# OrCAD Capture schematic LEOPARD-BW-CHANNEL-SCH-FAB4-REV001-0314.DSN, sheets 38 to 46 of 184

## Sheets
38 141_PVCCIN_CPU0_MOSFET_1: size C; title: PVCCIN_CPU0_MOSFET_1
39 140_PVCCIN_CPU0_Controller: size A3; title: PVCCIN_CPU0_CONTROLLER
40 004_CLOCK BLOCK DIAGRAM: title: CLOCK BLOCK DIAGRAM
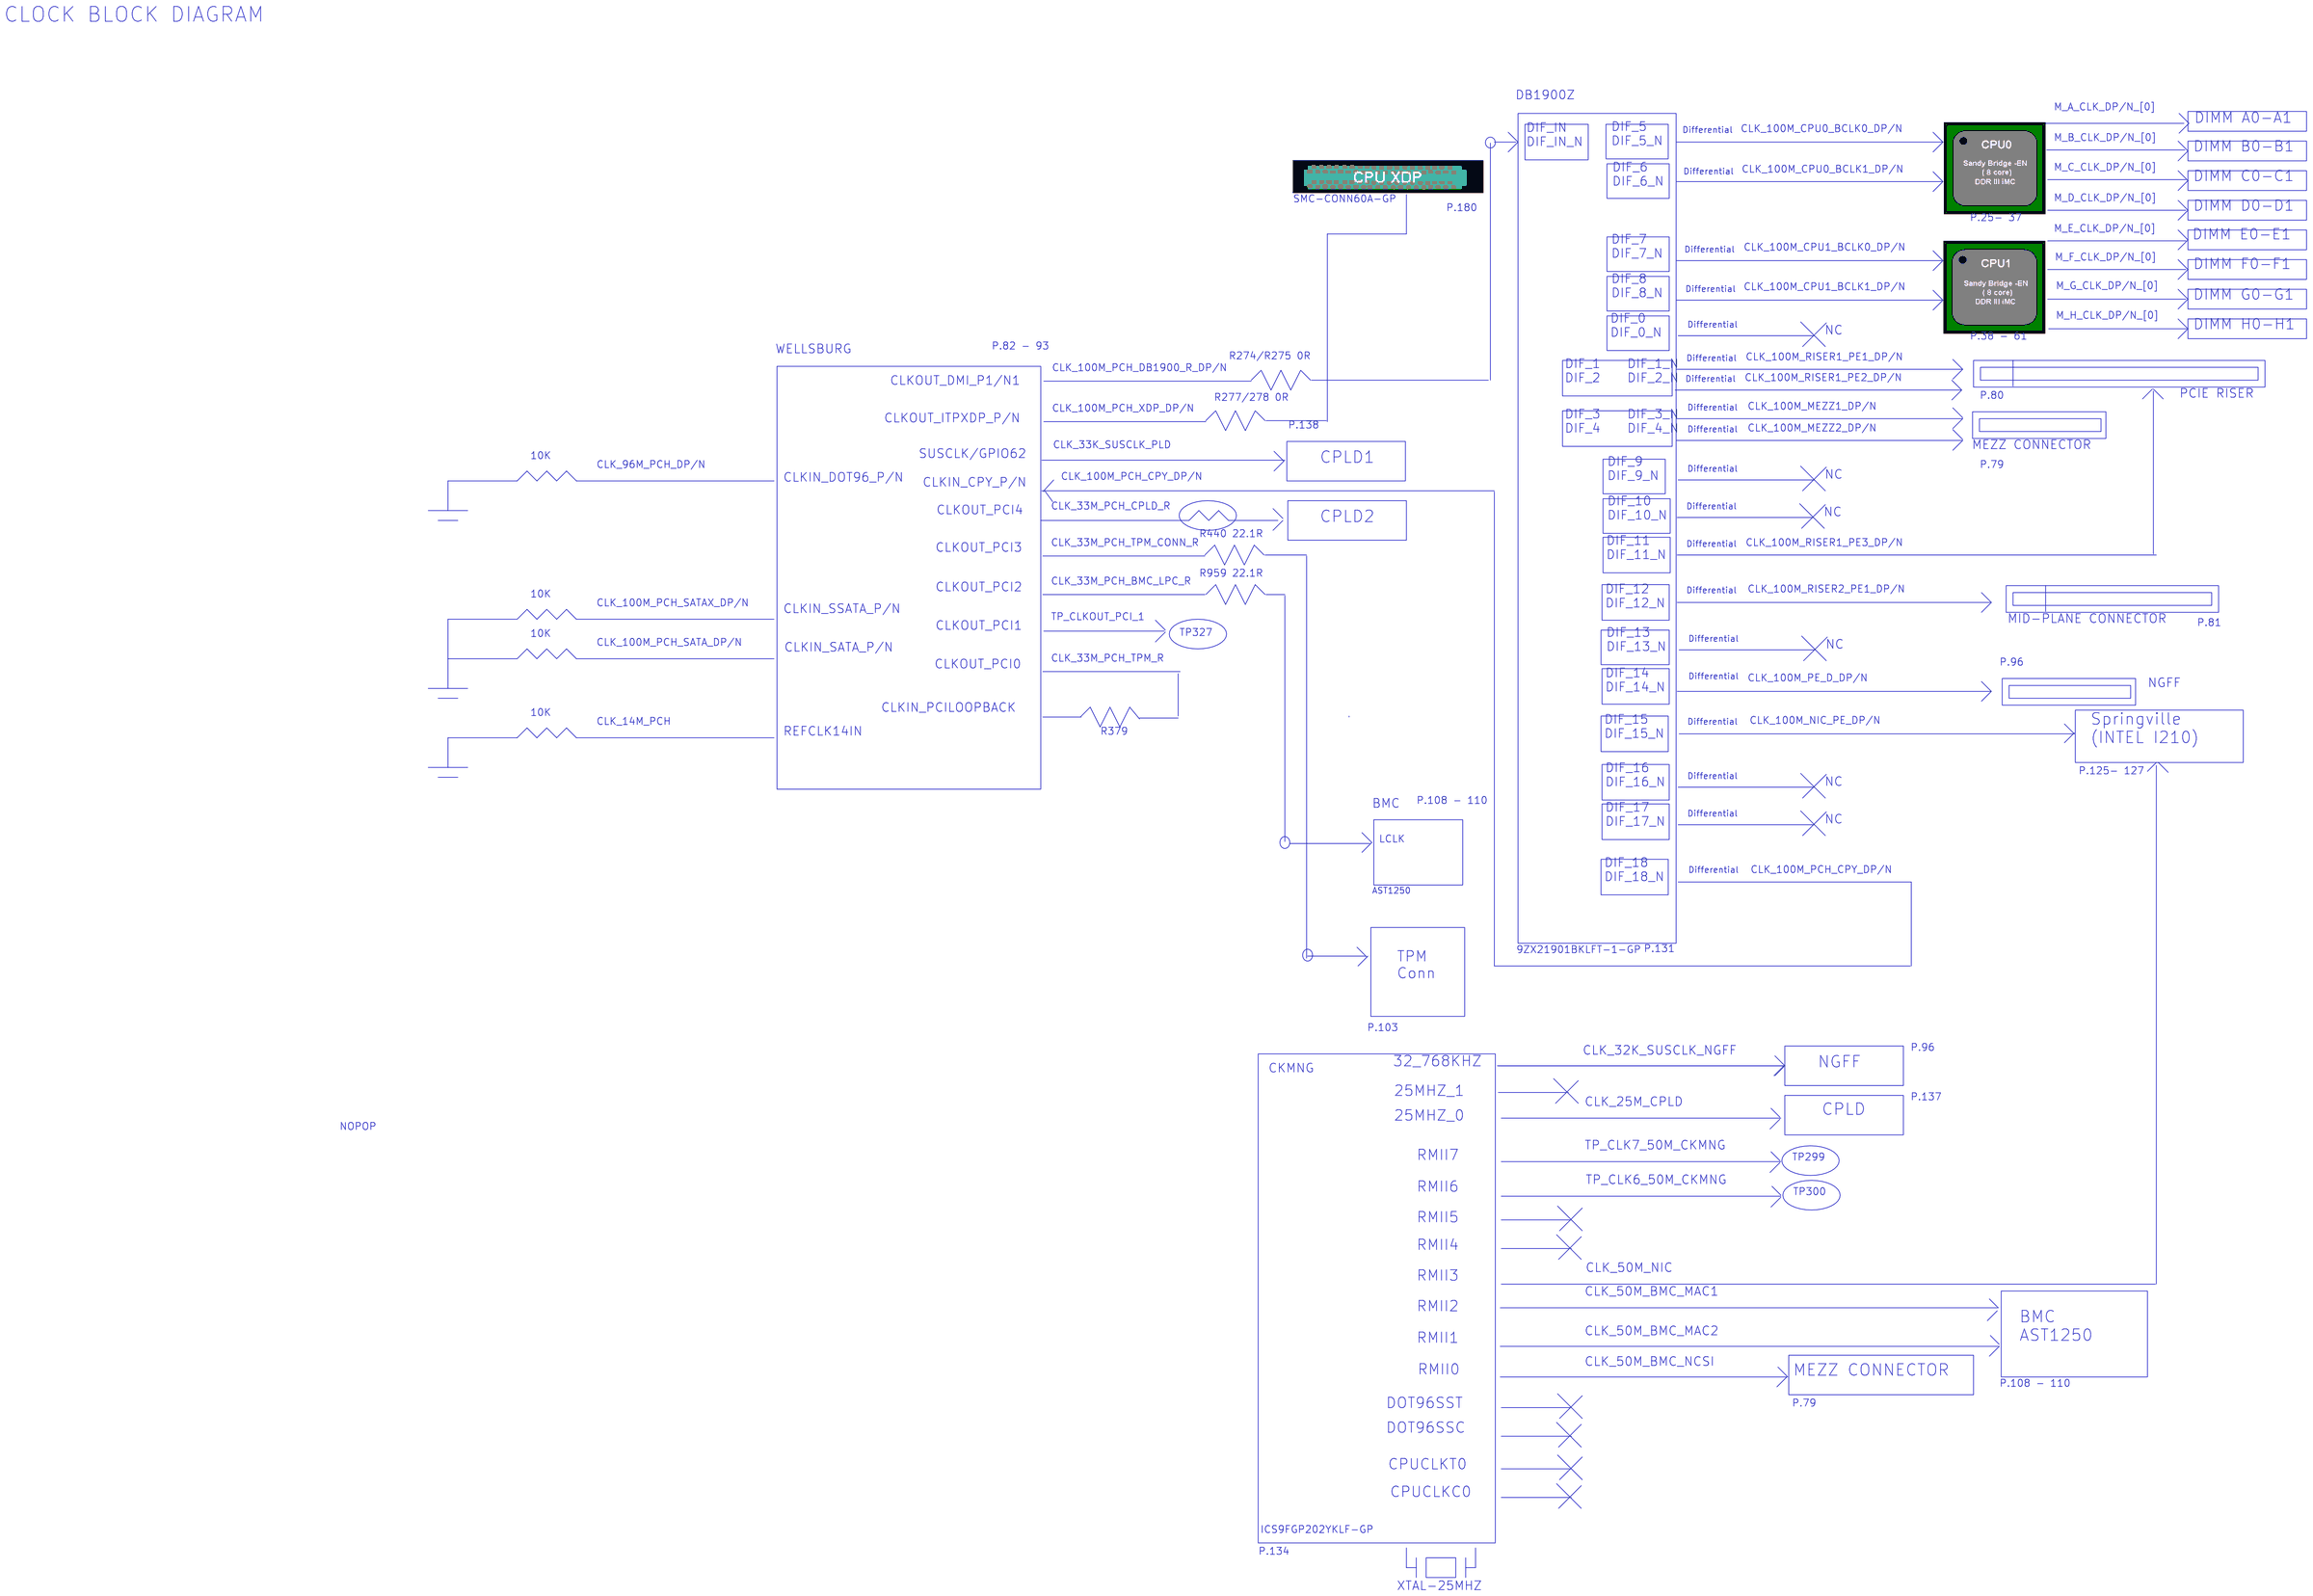
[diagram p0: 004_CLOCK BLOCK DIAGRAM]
41 007_SMBUS BLOCK DIAGRAM-CPU&PCH: title: SMBUS BLOCK DIAGRAM-CPU&PCH
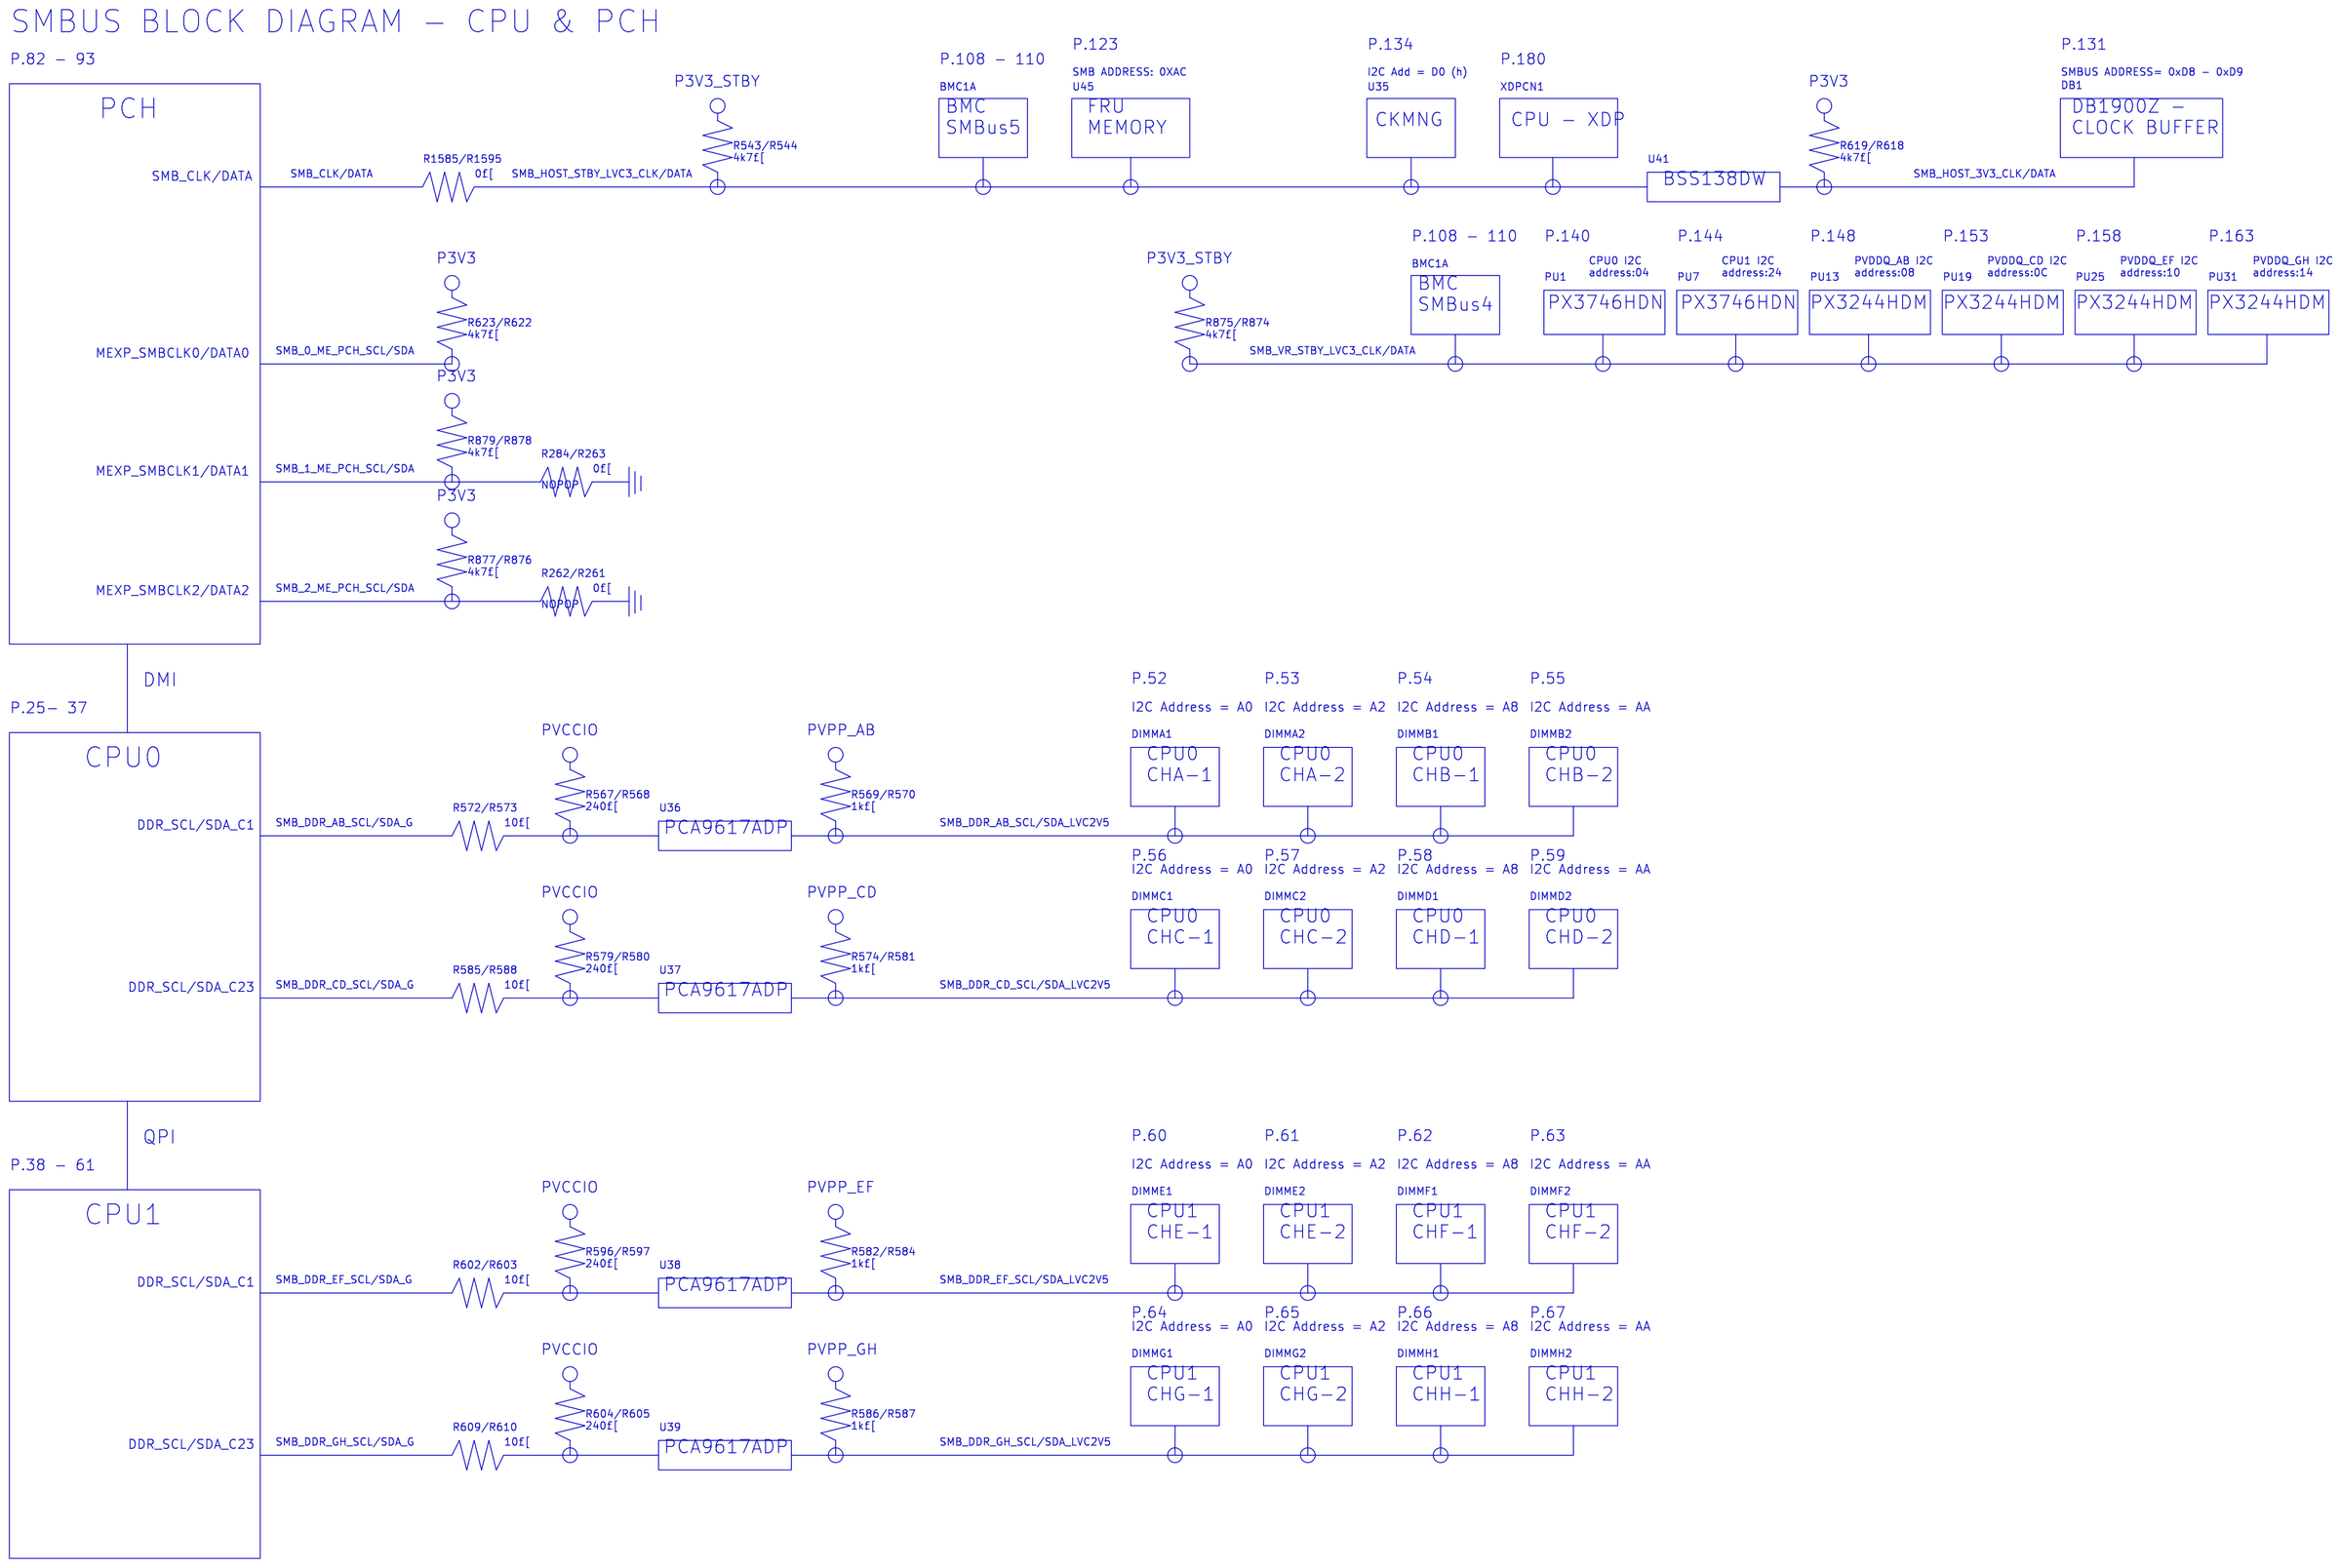
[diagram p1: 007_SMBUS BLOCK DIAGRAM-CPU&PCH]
42 006_SMBUS BLOCK DIAGRAM-BMC: title: SMBUS BLOCK DIAGRAM-BMC
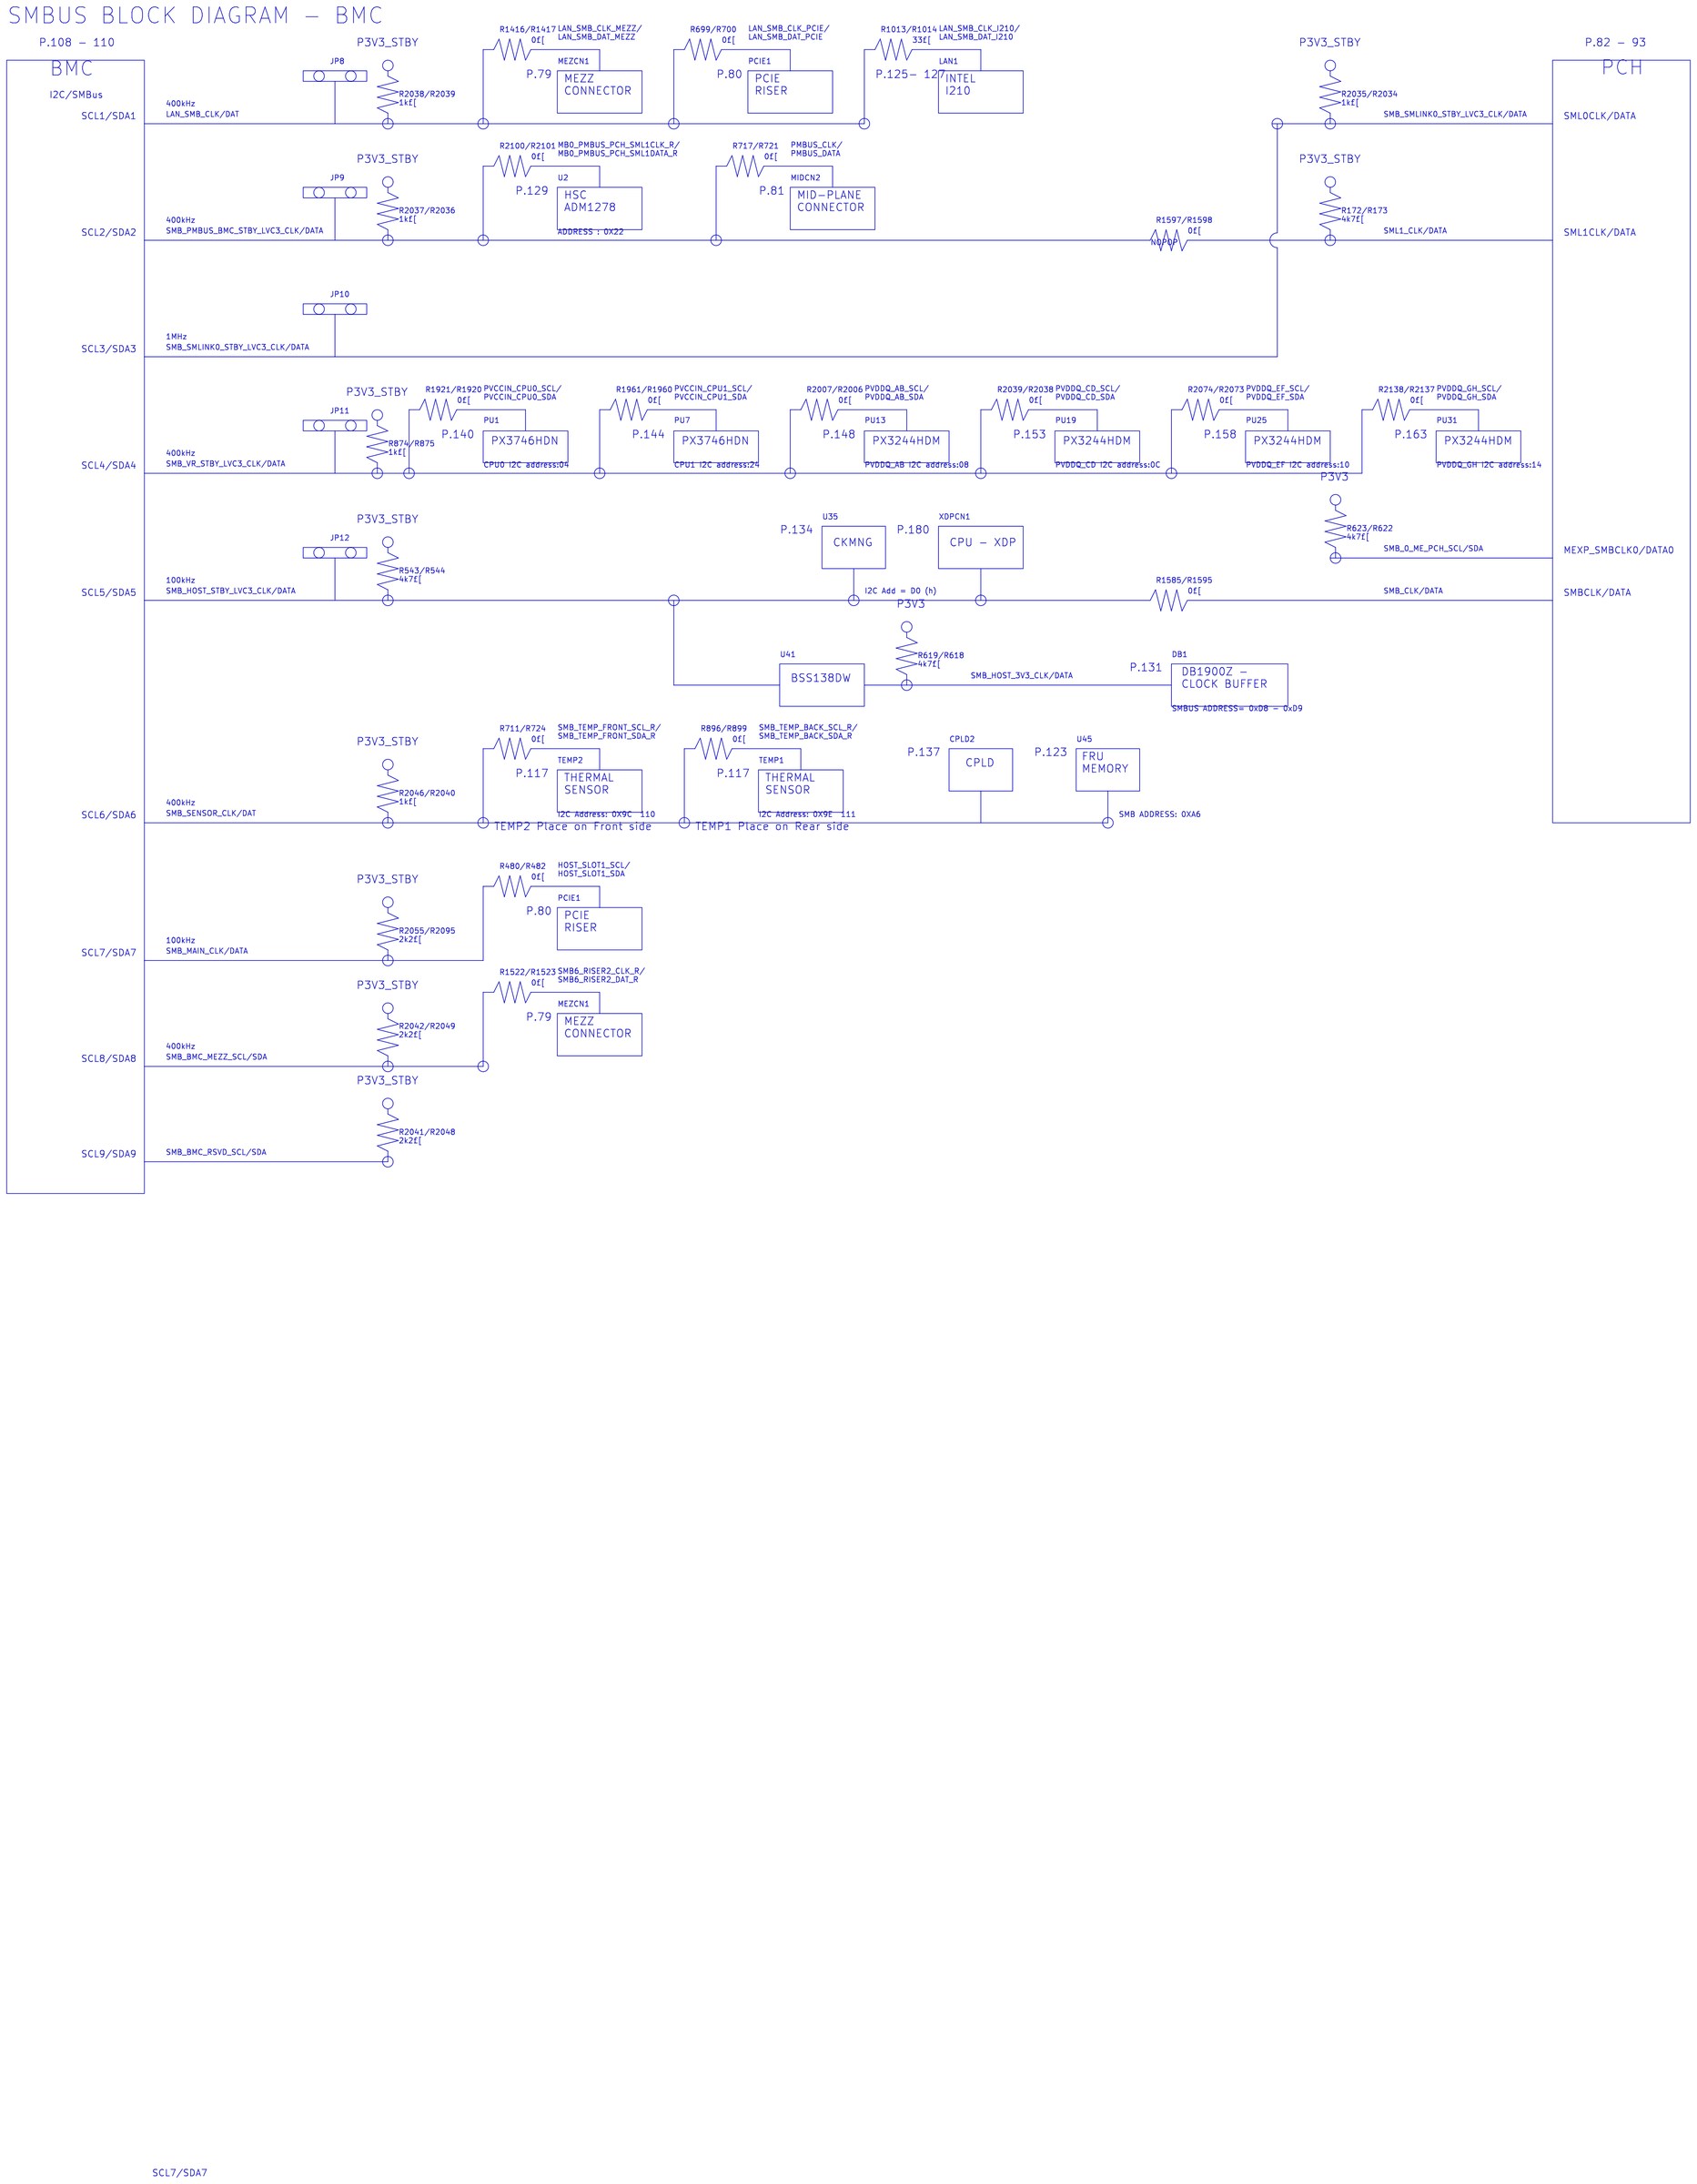
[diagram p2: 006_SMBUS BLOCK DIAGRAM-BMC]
43 184_CHANGE LIST: title: CHANGE LIST
44 183_SCREW HOLE: size A3; title: SCREW HOLE
45 182_POWER SEQUENCE CONTROL: size A3; title: POWER SEQUENCE CONTROL
46 181_CPU - JTAG: size A3; title: CPU - JTAG

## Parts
sheet 140_PVCCIN_CPU0_Controller
PC1087  SC1U10V2KX-4-GP  [C402H22]
PC1088  SCD1U16V2KX-3GP  [C402H22]
PC1089  SC1U10V2KX-4-GP  [C402H22]
PC1090  SCD1U16V2KX-3GP  [C402H22]
PC1094  SC1KP50V2KX-1GP  [C402H22]
PC1095  SC220P50V2KX-3GP  [C402H22]
PC1096  SC10U4V3MX-3-GP  [C603H40]
PC1097  SCD1U16V2KX-3GP  [C402H22]
PC1430  SC220P50V2JN-3GP  [C402H22]
PC1492  SC220P50V2JN-3GP  [C402H22]
PC7321  SCD47U6D3V2KX-1-GP  [C402H22]
PC7322  SCD47U6D3V2KX-1-GP  [C402H22]
PC7323  SCD47U6D3V2KX-1-GP  [C402H22]
PC7324  SCD47U6D3V2KX-1-GP  [C402H22]
PC7325  SCD47U6D3V2KX-1-GP  [C402H22]
PCN1  FCI-CON3-S1-GP  [68001-203HLF]
PQ5  NST3906F3T5G-GP-U  [SOT-1123CBE1006-1H16]
PR1911  0R2J-2-GP  [R402H16]
PR1914  1KR2F-3-GP  [R402H16]
PR1915  1KR2F-3-GP  [R402H16]
PR1916  0R2J-2-GP  [R402H16]
PR1917  0R2J-2-GP  [R402H16]
PR1918  0R2J-2-GP  [R402H16]
PR1922  16KR2F-GP  [R402H16]
PR1923  16KR2F-GP  [R402H16]
PR1924  16KR2F-GP  [R402H16]
PR1925  19K1R2F-GP  [R402H16]
PR1926  1KR2F-3-GP  [R402H16]
PR1927  10R3F-GP  [R603H22]
PR1928  0R2J-2-GP  [R402H16]
PR1929  0R0402-PAD-1-GP  [0R0402-PAD]
PR1931  49D9R2F-GP  [R402H16]
PR1932  100R2F-L1-GP-U  [R402H14]
PR1933  82R2J-1-GP  [R402H16]
PR1934  0R2J-2-GP  [R402H16]
PR1935  0R2J-2-GP  [R402H16]
PR1936  150R2F-1-GP  [R402H16]
PTP1  TPAD24  [TPAD24]
PU1  PX3746HDN-GP  [QFN48J6-G3437H36]
sheet 141_PVCCIN_CPU0_MOSFET_1
PC1221  SCD47U25V3KX-3-GP  [C603H36]
PC1222  SCD22U16V2KX-GP  [C402H22]
PC1227  SC1U10V2KX-4-GP  [C402H22]
PC1228  SC1U10V2KX-4-GP  [C402H22]
PC1229  SC10U16V5KX-1-GP  [C805H54]
PC1234  SCD47U25V3KX-3-GP  [C603H36]
PC1280  SC10U16V5KX-1-GP  [C805H54]
PC1281  SCD22U16V2KX-GP  [C402H22]
PC1282  SC1U10V2KX-4-GP  [C402H22]
PC1283  SC1U10V2KX-4-GP  [C402H22]
PC1284  SCD47U25V3KX-3-GP  [C603H36]
PC1362  SC10U16V5KX-1-GP  [C805H54]
PC1363  SC10U16V5KX-1-GP  [C805H54]
PC1364  SC10U16V5KX-1-GP  [C805H54]
PC1369  SC10U16V5KX-1-GP  [C805H54]
PC1370  SC10U16V5KX-1-GP  [C805H54]
PC1371  SC10U16V5KX-1-GP  [C805H54]
PC1372  SC10U16V5KX-1-GP  [C805H54]
PC1373  SCD22U16V2KX-GP  [C402H22]
PC1374  SC1U10V2KX-4-GP  [C402H22]
PC1375  SC1U10V2KX-4-GP  [C402H22]
PC1394  SCD1U16V2KX-3GP  [C402H22]
PC1395  SCD1U16V2KX-3GP  [C402H22]
PC1396  SC1U25V3KX-GP  [C603H36]
PC1403  SC1U25V3KX-GP  [C603H36]
PC1404  SC1U25V3KX-GP  [C603H36]
PC1405  SCD1U16V2KX-3GP  [C402H22]
PC1428  SCD1U16V2KX-3GP  [C402H22]
PC1429  SCD1U16V2KX-3GP  [C402H22]
PC1435  SCD1U16V2KX-3GP  [C402H22]
PG27  COPPER-CLOSE-GP-U  [CON2C-U]
PG28  COPPER-CLOSE-GP-U  [CON2C-U]
PG29  COPPER-CLOSE-GP-U  [CON2C-U]
PG30  COPPER-CLOSE-GP-U  [CON2C-U]
PG33  COPPER-CLOSE-GP-U  [CON2C-U]
PG34  COPPER-CLOSE-GP-U  [CON2C-U]
PL75  IND-150NH-15-GP  [L102078-254224H296]
PL76  IND-150NH-15-GP  [L102078-254224H296]
PL77  IND-150NH-15-GP  [L102078-254224H296]
PR24  0R2J-2-GP  [R402H16]
PR25  0R2J-2-GP  [R402H16]
PR26  0R2J-2-GP  [R402H16]
PR42  0R2J-2-GP  [R402H16]
PR43  0R2J-2-GP  [R402H16]
PR44  0R2J-2-GP  [R402H16]
PR2174  1R2F-GP  [R402H16]
PR2178  1R2F-GP  [R402H16]
PR2181  1R2F-GP  [R402H16]
PR2205  0R3J-6-GP  [R603H22]
PR2209  0R3J-6-GP  [R603H22]
PR2215  0R3J-6-GP  [R603H22]
PR2227  10KR2F-2-GP  [R402H16]
PR2228  10KR2F-2-GP  [R402H16]
PR2229  10KR2F-2-GP  [R402H16]
PR6626  562R2F-GP  [R402H16]
PR6627  562R2F-GP  [R402H16]
PR6629  562R2F-GP  [R402H16]
PR6630  562R2F-GP  [R402H16]
PR6631  562R2F-GP  [R402H16]
PR6632  562R2F-GP  [R402H16]
PTP7  TPAD24  [TPAD24]
PTP8  TPAD24  [TPAD24]
PTP9  TPAD24  [TPAD24]
PTP10  TPAD24  [TPAD24]
PTP11  TPAD24  [TPAD24]
PTP12  TPAD24  [TPAD24]
PU178  TDA21232-GP  [QFN31G5-G4P-7H38]
PU179  TDA21232-GP  [QFN31G5-G4P-7H38]
PU180  TDA21232-GP  [QFN31G5-G4P-7H38]
sheet 181_CPU - JTAG
C714  SC1U25V3KX-GP  [C603H36]
C715  SCD01U25V2KX-3GP  [C402H22]
C716  SC1U25V3KX-GP  [C603H36]
C717  SCD01U25V2KX-3GP  [C402H22]
C722  SC1U25V3KX-GP  [C603H36]
C727  SC1U25V3KX-GP  [C603H36]
C909  SC1U25V3KX-GP  [C603H36]
R300  0R2J-2-GP  [R402H16]
R303  0R2J-2-GP  [R402H16]
R328  0R2J-2-GP  [R402H16]
R329  0R2J-2-GP  [R402H16]
R426  0R2J-2-GP  [R402H16]
R431  0R2J-2-GP  [R402H16]
R470  2KR2F-3-GP  [R402H16]
R612  51R2F-2-GP  [R402H16]
R615  51R2F-2-GP  [R402H16]
R626  51R2F-2-GP  [R402H16]
R702  100R2F-L1-GP-U  [R402H14]
R1000  75R2F-2-GP  [R402H16]
R1001  75R2F-2-GP  [R402H16]
R1003  75R2F-2-GP  [R402H16]
R1006  1KR2F-3-GP  [R402H16]
R1007  1KR2F-3-GP  [R402H16]
R1213  1KR2F-3-GP  [R402H16]
R1214  1KR2F-3-GP  [R402H16]
R1237  100R2F-L1-GP-U  [R402H14]
R1245  100R2F-L1-GP-U  [R402H14]
R1246  100R2F-L1-GP-U  [R402H14]
R1247  1KR2F-3-GP  [R402H16]
TP313  TPAD24  [TPAD24]
TP314  TPAD24  [TPAD24]
U69  NC7SB3157P6X-2GP  [UMT6H44]
U70  NC7SB3157P6X-2GP  [UMT6H44]
U71  74LVC1G02GW-1-GP  [SC70-5H44]
U72  NC7SZ66P5X-1GP  [SC70-5H44]
U146  GTL2034PW-GP  [TSOIC14H44]
sheet 182_POWER SEQUENCE CONTROL
D15  BAT54-7-F-GP  [SOT-23-6H44]
D16  BAT54-7-F-GP  [SOT-23-6H44]
D17  BAT54-7-F-GP  [SOT-23-6H44]
D18  BAT54-7-F-GP  [SOT-23-6H44]
D19  BAT54-7-F-GP  [SOT-23-6H44]
D33  BAT54-7-F-GP  [SOT-23-6H44]
D34  BAT54-7-F-GP  [SOT-23-6H44]
D35  BAT54-7-F-GP  [SOT-23-6H44]
sheet 183_SCREW HOLE
CLIP1  AMP-CON2-13-GP  [G800U305032D1EU]
CLIP2  AMP-CON2-13-GP  [G800U305032D1EU]
H1  GEN276X162R197X296-6-F-A-GP  [GEN276X162R197X296-6-F-A]
H2  GEN276X162R197X296-6-F-A-GP  [GEN276X162R197X296-6-F-A]
H3  GEN276X162R197X296-6-F-A-GP  [GEN276X162R197X296-6-F-A]
H4  GEN276X162R197X296-6-F-A-GP  [GEN276X162R197X296-6-F-A]
H5  GEN276X162R197X296-6-F-A-GP  [GEN276X162R197X296-6-F-A]
H6  GEN276X162R197X296-6-F-A-GP  [GEN276X162R197X296-6-F-A]
H7  GEN276X162R197X296-6-F-A-GP  [GEN276X162R197X296-6-F-A]
H8  STFT363B238R224H453-GP  [STFT363B238R224H453]
H10  HOLE  [HOLE256R126]

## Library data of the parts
PC1087 PC1089 PC1227 PC1228 PC1282 PC1283 PC1374 PC1375 = SC1U10V2KX-4-GP: CHIP CAP C 1U 10V K 0402 X6S; GREENDFACTOR: R2_SA;HF_SA;; Package Type: SMD-BCG6; Part Number: 78.10523.8FL; SPEC: http://wpqssvr.wistron.com.tw:7001/wpqs/servlet/COM.qpart.Attachment?PartNumber=78.10523.8FL
PC1088 PC1090 = SCD1U16V2KX-3GP: CHIP CAP C 0.1U 16V K0402 X7R; GREENDFACTOR: R2_SA;HF_SA;G_SA;; MAIN_SOURCE: M; Package Type: SMD-BCG; Part Number: 78.10421.2FL; SPEC: http://wpqssvr.wistron.com.tw:7001/wpqs/servlet/COM.qpart.Attachment?PartNumber=78.10421.2FL
PC1094 = SC1KP50V2KX-1GP: CHIP CAP 1000P50V K0402 X7R(RO; GREENDFACTOR: R2_SA;HF_SA;G_SA;; MAIN_SOURCE: M; Package Type: SMD-BCG; Part Number: 78.10224.2FL; SPEC: http://wpqssvr.wistron.com.tw:7001/wpqs/servlet/COM.qpart.Attachment?PartNumber=78.10224.2FL
PC1095 = SC220P50V2KX-3GP: CHIP CAP 220P50V K0402 X7R(ROH; GREENDFACTOR: R2_SA;HF_SA;G_SA;; MAIN_SOURCE: M; Package Type: SMD-BCG; Part Number: 78.22124.2FL; SPEC: http://wpqssvr.wistron.com.tw:7001/wpqs/servlet/COM.qpart.Attachment?PartNumber=78.22124.2FL
PC1096 = SC10U4V3MX-3-GP: CHIP CAP C 10U 4V M0603 X6S; GREENDFACTOR: R2_C;; POP?: 078.1061T.08B1; Package Type: SMD-BCG6; Part Number: 78.1061T.8BL; SPEC: http://wpqssvr.wistron.com.tw:7001/wpqs/servlet/COM.qpart.Attachment?PartNumber=78.1061T.8BL
PC1097 = SCD1U16V2KX-3GP: CHIP CAP C 0.1U 16V K0402 X7R; CATEGORIES: CAP_1.xV; GREENDFACTOR: R2_SA;HF_SA;G_SA;; MAIN_SOURCE: M; Part Number: 78.10421.2FL; Part Type: SMD-BCG; SPEC: http://wpqssvr.wistron.com.tw:7001/wpqs/servlet/COM.qpart.Attachment?PartNumber=78.10421.2FL
PC1430 PC1492 = SC220P50V2JN-3GP: CHIP CAP C 220P 50V J0402 NPO; GREENDFACTOR: R2_SA;HF_SA;G_SA;; Package Type: SMD-BCG; Part Number: 78.22134.1FL; SPEC: http://wpqssvr.wistron.com.tw:7001/wpqs/servlet/COM.qpart.Attachment?PartNumber=78.22134.1FL
PC7321-PC7325 = SCD47U6D3V2KX-1-GP: CHIP CAP C 0.47U 6.3V K 0402 X6S; GREENDFACTOR: R2_SA;HF_SA;; Package Type: SMD-BCG3; Part Number: 78.47420.8FL; SPEC: http://wpqssvr.wistron.com.tw:7001/wpqs/servlet/COM.qpart.Attachment?PartNumber=78.47420.8FL
PCN1 = FCI-CON3-S1-GP: HEAD ML 1R3P ST 68001-203HLF; GREENDFACTOR: R2_SA;; Part Number: 21.61084.103; Part Type: CONN-G4; SPEC: http://wpqssvr.wistron.com.tw:7001/wpqs/servlet/COM.qpart.Attachment?PartNumber=21.61084.103
PQ5 = NST3906F3T5G-GP-U: XTOR NST3906F3T5G PNP SOT-1123; GREENDFACTOR: R2_SA;HF_SA;; Package Type: DISCRET-G5; Part Number: 84.03906.01K; SPEC: http://wpqssvr.wistron.com.tw:7001/wpqs/servlet/COM.qpart.Attachment?PartNumber=84.03906.01K
PR42-PR44 PR1911 PR1916-PR1918 PR1934 PR1935 = 0R2J-2-GP: CHIP RES 0 J 1/16W 0402; GREENDFACTOR: R2_SA;HF_SA;G_SA;; Package Type: SMD-RG; Part Number: 63.R0034.1DL; SPEC: http://wpqssvr.wistron.com.tw:7001/wpqs/servlet/COM.qpart.Attachment?PartNumber=63.R0034.1DL
PR1914 PR1915 PR1926 = 1KR2F-3-GP: CHIP RES 1K F 1/16W 0402; GREENDFACTOR: R2_SA;HF_SA;G_SA;; Package Type: SMD-RG; Part Number: 64.10015.6DL; SPEC: http://wpqssvr.wistron.com.tw:7001/wpqs/servlet/COM.qpart.Attachment?PartNumber=64.10015.6DL
PR1922 PR1923 = 16KR2F-GP: CHIP RES 16K F 1/16W 0402; GREENDFACTOR: R2_SA;HF_SA;G_SA;; Module: VR_PVCORE_CPU; POP?: NOPOP; Package Type: SMD-RG; Part Number: 64.16025.6DL; Quotation: 8_1; SPEC: http://wpqssvr.wistron.com.tw:7001/wpqs/servlet/COM.qpart.Attachment?PartNumber=64.16025.6DL
PR1924 = 16KR2F-GP: CHIP RES 16K F 1/16W 0402; GREENDFACTOR: R2_SA;HF_SA;G_SA;; Module: VR_PVCORE_CPU; Package Type: SMD-RG; Part Number: 64.16025.6DL; Quotation: 8_1; SPEC: http://wpqssvr.wistron.com.tw:7001/wpqs/servlet/COM.qpart.Attachment?PartNumber=64.16025.6DL
PR1925 = 19K1R2F-GP: CHIP RES 19.1K F 1/16W 0402; GREENDFACTOR: R2_SA;HF_SA;G_SA;; Part Number: 64.19125.6DL; Part Type: RCL_GP; SPEC: http://wpqssvr.wistron.com.tw:7001/wpqs/servlet/COM.qpart.Attachment?PartNumber=64.19125.6DL
PR1927 = 10R3F-GP: CHIP RES 10 F 1/10W 0603; GREENDFACTOR: R2_SA;HF_SA;G_SA;; Level: SMD; Package Type: RCL_GP; Part Number: 64.10R05.55L; Part Type: RCL_GP; SPEC: http://wpqssvr.wistron.com.tw:7001/wpqs/servlet/COM.qpart.Attachment?PartNumber=64.10R05.55L; Status: POP
PR1928 = 0R2J-2-GP: CHIP RES 0 J 1/16W 0402; GREENDFACTOR: R2_SA;HF_SA;G_SA;; Part Number: 63.R0034.1DL; Part Type: SMD-RG; SPEC: http://wpqssvr.wistron.com.tw:7001/wpqs/servlet/COM.qpart.Attachment?PartNumber=63.R0034.1DL
PR1929 = 0R0402-PAD-1-GP: DUMMY PAD WITH WIRE RES 0 0402; GREENDFACTOR: R_C;; Module: VR_CPU_PVCC; Package Type: SMD-RG2; Part Number: ZZ.R0402.001; Part Type: SMD-RG2; Quotation: 8_1; SPEC: http://wpqssvr.wistron.com.tw:7001/wpqs/servlet/COM.qpart.Attachment?PartNumber=ZZ.R0402.001
PR1931 = 49D9R2F-GP: CHIP RES 49.9 F 1/16W 0402; GREENDFACTOR: R2_SA;HF_SA;G_SA;; Package Type: RCL_GP; Part Number: 64.49R95.6DL; SPEC: http://wpqssvr.wistron.com.tw:7001/wpqs/servlet/COM.qpart.Attachment?PartNumber=64.49R95.6DL
PR1932 = 100R2F-L1-GP-U: CHIP RES 100 F 1/16W 0402; GREENDFACTOR: R2_SA;HF_SA;G_SA;; Package Type: SMD-RG; Part Number: 64.10005.6DL; SPEC: http://wpqssvr.wistron.com.tw:7001/wpqs/servlet/COM.qpart.Attachment?PartNumber=64.10005.6DL
PR1933 = 82R2J-1-GP: CHIP RES 82 J 1/16W 0402; GREENDFACTOR: R2_SA;HF_SA;G_SA;; POP?: NOPOP; Package Type: RCL_GP; Part Number: 63.82034.1DL; SPEC: http://wpqssvr.wistron.com.tw:7001/wpqs/servlet/COM.qpart.Attachment?PartNumber=63.82034.1DL
PR1936 = 150R2F-1-GP: CHIP RES 150 F 1/16W 0402; GREENDFACTOR: R2_SA;HF_SA;G_SA;; Package Type: SMD-RG; Part Number: 64.15005.6DL; SPEC: http://wpqssvr.wistron.com.tw:7001/wpqs/servlet/COM.qpart.Attachment?PartNumber=64.15005.6DL
PTP1 PTP7-PTP12 = TPAD24: 24 MILS TEST PAD; GREENDFACTOR: Regular;; Package Type: DISCRET2; Part Number: ZZ.PAD24.001; SPEC: http://wpqssvr.wistron.com.tw:7001/wpqs/servlet/COM.qpart.Attachment?PartNumber=ZZ.PAD24.001
PU1 = PX3746HDN-GP: IC PWM CTRL PX3746HDN QFN 48P; GREENDFACTOR: R2_SA;; Package Type: ASIC-G5; Part Number: 074.03746.0073; SPEC: http://wpqssvr.wistron.com.tw:7001/wpqs/servlet/COM.qpart.Attachment?PartNumber=074.03746.0073
PC1221 PC1234 PC1284 = SCD47U25V3KX-3-GP: CHIP CAP C 0.47U 25V K0603 X7R; GREENDFACTOR: R2_SA;HF_SA;G_SA;; Part Number: 78.47422.2BL; Part Type: SMD-BCG5; SPEC: http://wpqssvr.wistron.com.tw:7001/wpqs/servlet/COM.qpart.Attachment?PartNumber=78.47422.2BL
PC1222 PC1281 PC1373 = SCD22U16V2KX-GP: CHIP CAP C 0.22U 16V K0402 X7R; GREENDFACTOR: R2_SA;HF_SA;G_SA;; Package Type: SMD-BCG4; Part Number: 78.22421.2FL; SPEC: http://wpqssvr.wistron.com.tw:7001/wpqs/servlet/COM.qpart.Attachment?PartNumber=78.22421.2FL; Size: 0402; Type: X7R
PC1229 PC1280 PC1362-PC1364 PC1369-PC1372 = SC10U16V5KX-1-GP: CHIP CAP C 10U 16V K0805 X6S; GREENDFACTOR: R2_SA;; Package Type: SMD-BCG5; Part Number: 78.10621.81L; SPEC: http://wpqssvr.wistron.com.tw:7001/wpqs/servlet/COM.qpart.Attachment?PartNumber=78.10621.81L
PC1394 PC1395 PC1405 PC1428 PC1429 PC1435 = SCD1U16V2KX-3GP: CHIP CAP C 0.1U 16V K0402 X7R; GREENDFACTOR: R2_SA;HF_SA;G_SA;; MAIN_SOURCE: M; Package Type: SMD-BCG; Part Number: 78.10421.2FL; SPEC: http://wpqssvr.wistron.com.tw:7001/wpqs/servlet/COM.qpart.Attachment?PartNumber=78.10421.2FL; Size: 0402; Type: X7R
PC1396 PC1403 PC1404 = SC1U25V3KX-GP: CHIP CAP C 1U 25V K0603 X7R; GREENDFACTOR: R2_SA;HF_SA;G_SA;; Package Type: SMD-BCG; Part Number: 78.10522.2BL; SPEC: http://wpqssvr.wistron.com.tw:7001/wpqs/servlet/COM.qpart.Attachment?PartNumber=78.10522.2BL
PG27-PG30 PG33 PG34 = COPPER-CLOSE-GP-U: COPPER CLOSE; GREENDFACTOR: Regular;; Package Type: DISCRET-G9; Part Number: ZZ.CON2C.XXX; SPEC: http://wpqssvr.wistron.com.tw:7001/wpqs/servlet/COM.qpart.Attachment?PartNumber=ZZ.CON2C.XXX
PL75-PL77 = IND-150NH-15-GP: CHIP IND 150NH K FP1007R3-R15-R; GREENDFACTOR: R2_SA;; Part Number: 68.1512N.10E; Part Type: DISCRET-G9; SPEC: http://wpqssvr.wistron.com.tw:7001/wpqs/servlet/COM.qpart.Attachment?PartNumber=68.1512N.10E
PR24-PR26 = 0R2J-2-GP: CHIP RES 0 J 1/16W 0402; GREENDFACTOR: R2_SA;HF_SA;G_SA;; POP?: NOPOP; Package Type: SMD-RG; Part Number: 63.R0034.1DL; SPEC: http://wpqssvr.wistron.com.tw:7001/wpqs/servlet/COM.qpart.Attachment?PartNumber=63.R0034.1DL
PR2174 PR2178 PR2181 = 1R2F-GP: CHIP RES 1 F 1/16W 0402; GREENDFACTOR: R2_SA;HF_SA;G_SA;; Package Type: SMD-RG; Part Number: 64.1R005.6DL; SPEC: http://wpqssvr.wistron.com.tw:7001/wpqs/servlet/COM.qpart.Attachment?PartNumber=64.1R005.6DL
PR2205 PR2209 PR2215 = 0R3J-6-GP: CHIP RES 0 J 1/10W 0603; GREENDFACTOR: R2_SA;HF_SA;G_SA;; Part Number: 63.R0033.15L; Part Type: SMD-RG1; SPEC: http://wpqssvr.wistron.com.tw:7001/wpqs/servlet/COM.qpart.Attachment?PartNumber=63.R0033.15L
PR2227-PR2229 = 10KR2F-2-GP: CHIP RES 10K F 1/16W 0402; GREENDFACTOR: R2_SA;HF_SA;G_SA;; POP?: NOPOP; Package Type: SMD-RG; Part Number: 64.10025.6DL; SPEC: http://wpqssvr.wistron.com.tw:7001/wpqs/servlet/COM.qpart.Attachment?PartNumber=64.10025.6DL
PR6626 PR6627 PR6629-PR6632 = 562R2F-GP: CHIP RES 562 F 1/16W 0402; GREENDFACTOR: R2_SA;HF_SA;G_SA;; Package Type: SMD-RG; Part Number: 64.56205.6DL; SPEC: http://wpqssvr.wistron.com.tw:7001/wpqs/servlet/COM.qpart.Attachment?PartNumber=64.56205.6DL
PU178-PU180 = TDA21232-GP: IC PWM TDA21232 IQFN 32P; GREENDFACTOR: R2_C;; Part Number: 074.21232.0073; Part Type: DISCRET-GB1; SPEC: http://wpqssvr.wistron.com.tw:7001/wpqs/servlet/COM.qpart.Attachment?PartNumber=074.21232.0073
C714 C716 C722 C727 C909 = SC1U25V3KX-GP: CHIP CAP C 1U 25V K0603 X7R; GREENDFACTOR: R2_SA;HF_SA;G_SA;; Part Number: 78.10522.2BL; Part Type: SMD-BCG; SPEC: http://wpqssvr.wistron.com.tw:7001/wpqs/servlet/COM.qpart.Attachment?PartNumber=78.10522.2BL
C715 C717 = SCD01U25V2KX-3GP: CHIP 0.01U 25V K0402 X7R(ROHS); Category: XDP; DESCRIPTIO: CHIP 0.01U 25V K0402 X7R(ROHS); GREENDFACTOR: R2_SA;HF_SA;G_SA;; Package Type: SMD-BCG; Part Number: 78.10322.2FL; Part Type: SMD-BCG; SPEC: http://wpqssvr.wistron.com.tw:7001/wpqs/servlet/COM.qpart.Attachment?PartNumber=78.10322.2FL; VENDORPARTNUMBER: 04023C103KAT2A/C1005X7R103KFT/GRM155R71E103KA01D/223891715636/CL05B103KA5NNNC/TMK105BJ103KV-F/C1005X7R1E103KT000F
R300 R328 = 0R2J-2-GP: CHIP RES 0 J 1/16W 0402; Category: PCH; DESCRIPTIO: CHIP RES 0 J 1/16W 0402; GREENDFACTOR: R2_SA;HF_SA;G_SA;; Package Type: SMD-RG; Part Number: 63.R0034.1DL; Part Type: SMD-RG; SPEC: http://wpqssvr.wistron.com.tw:7001/wpqs/servlet/COM.qpart.Attachment?PartNumber=63.R0034.1DL; VENDORPARTNUMBER: RM04JTN0/RTT02000JTH/RR0510X-000-XN/RC0402JR-070RL/WR04X000 PTL
R303 R329 = 0R2J-2-GP: CHIP RES 0 J 1/16W 0402; Category: PCH; DESCRIPTIO: CHIP RES 0 J 1/16W 0402; GREENDFACTOR: R2_SA;HF_SA;G_SA;; POP?: NOPOP; Package Type: SMD-RG; Part Number: 63.R0034.1DL; Part Type: SMD-RG; SPEC: http://wpqssvr.wistron.com.tw:7001/wpqs/servlet/COM.qpart.Attachment?PartNumber=63.R0034.1DL; VENDORPARTNUMBER: RM04JTN0/RTT02000JTH/RR0510X-000-XN/RC0402JR-070RL/WR04X000 PTL
R426 R431 = 0R2J-2-GP: CHIP RES 0 J 1/16W 0402; Category: LOM - i350; DESCRIPTIO: CHIP RES 0 J 1/16W 0402; GREENDFACTOR: R2_SA;HF_SA;G_SA;; POP?: NOPOP; Package Type: SMD-RG; Part Number: 63.R0034.1DL; Part Type: SMD-RG; SPEC: http://wpqssvr.wistron.com.tw:7001/wpqs/servlet/COM.qpart.Attachment?PartNumber=63.R0034.1DL; VENDORPARTNUMBER: RM04JTN0/RTT02000JTH/RR0510X-000-XN/RC0402JR-070RL/WR04X000 PTL
R470 = 2KR2F-3-GP: CHIP RES 2K F 1/16W 0402; Category: internal conn; DESCRIPTIO: CHIP RES 2K F 1/16W 0402; GREENDFACTOR: R2_SA;HF_SA;G_SA;; Package Type: SMD-RG; Part Number: 64.20015.6DL; Part Type: SMD-RG; SPEC: http://wpqssvr.wistron.com.tw:7001/wpqs/servlet/COM.qpart.Attachment?PartNumber=64.20015.6DL; VENDORPARTNUMBER: RM04FTN2001 / RTT022001FTH / RR0510S-202-FN / RC0402FR-072KL/WR04X2001FTL
R612 R615 R626 = 51D1R2F-GP: CHIP RES 51 F 1/16W 0402; Category: XDP; DESCRIPTIO: CHIP RES 51.1 F 1/16W 0402; GREENDFACTOR: R2_SA;HF_SA;G_SA;; Package Type: SMD-RG; Part Number: 64.51R05.6DL; Part Type: SMD-RG; SPEC: http://wpqssvr.wistron.com.tw:7001/wpqs/servlet/COM.qpart.Attachment?PartNumber=64.51R05.6DL; VENDORPARTNUMBER: RM04FTN51R0/RTT0251R0FTH/RR0510S-510-FN/RC0402FR-0751RL/WR04X51R0FTL
R702 R1237 R1245 R1246 = 100R2F-L1-GP-U: CHIP RES 100 F 1/16W 0402; Category: BMC; DESCRIPTIO: CHIP RES 100 F 1/16W 0402; GREENDFACTOR: R2_SA;HF_SA;G_SA;; Package Type: SMD-RG; Part Number: 64.10005.6DL; Part Type: SMD-RG; SPEC: http://wpqssvr.wistron.com.tw:7001/wpqs/servlet/COM.qpart.Attachment?PartNumber=64.10005.6DL; VENDORPARTNUMBER: RM04FTN1000 / RTT021000FTH / RR0510S-1000-FN / RC0402FR-07100RL/WR04X1000FTL
R1000 R1001 R1003 = 75R2F-2-GP: CHIP RES 75 F 1/16W 0402; Category: XDP; DESCRIPTIO: CHIP RES 75 F 1/16W 0402; GREENDFACTOR: R2_SA;HF_SA;G_SA;; Package Type: SMD-RG; Part Number: 64.75R05.6DL; Part Type: SMD-RG; SPEC: http://wpqssvr.wistron.com.tw:7001/wpqs/servlet/COM.qpart.Attachment?PartNumber=64.75R05.6DL; VENDORPARTNUMBER: RM04FTN75R0 / RTT0275R0FTH / RR0510S-750-FN / RC0402FR-0775RL/WR04X75R0FTL
R1006 R1007 R1213 R1214 R1247 = 1KR2F-3-GP: CHIP RES 1K F 1/16W 0402; Category: internal conn; GREENDFACTOR: R2_SA;HF_SA;G_SA;; Package Type: SMD-RG; Part Number: 64.10015.6DL; Part Type: SMD-RG; SPEC: http://wpqssvr.wistron.com.tw:7001/wpqs/servlet/COM.qpart.Attachment?PartNumber=64.10015.6DL; VENDORPARTNUMBER: RM04FTN1001 / RTT021001FTH / RR0510S-1001-FN / RC0402FR-071KL/WR04X1001FTL
TP313 TP314 = TPAD24: 24 MILS TEST PAD; Part Number: ZZ.PAD24.001; Part Type: DISCRET2
U69 U70 = NC7SB3157P6X-2GP: IC SW NC7SB3157P6X SC70(L/F); Alternate: 73.03157.B0H; Category: XDP; Change to: 73.03157.A0J; DESCRIPTIO: IC SW NC7SB3157P6X SC70(L/F); GREENDFACTOR: R2_SA;; Note: The same as CRB; Package Type: DISCRET-G; Part Number: 73.03157.D0H; Part Type: DISCRET-G; SPEC: http://wpqssvr.wistron.com.tw:7001/wpqs/servlet/COM.qpart.Attachment?PartNumber=73.03157.D0H; VENDORPARTNUMBER: NC7SB3157P6X
U71 = 74LVC1G02GW-1-GP: IC CMOS 74LVC1G02GW SOT353-1; Alternate: 73.01G02.DHH,73.7SZ02.BAH; Category: CPU; DESCRIPTIO: IC CMOS 74LVC1G02GW SOT353-1; GREENDFACTOR: R2_SA;; Note: The same as CRB; Package Type: DISCRET-G2; Part Number: 73.01G02.AHG; Part Type: DISCRET-G2; SPEC: http://wpqssvr.wistron.com.tw:7001/wpqs/servlet/COM.qpart.Attachment?PartNumber=73.01G02.AHG; VENDORPARTNUMBER: 74LVC1G02GW
U72 = NC7SZ66P5X-1GP: IC CMOS NC7SZ66P5X_NL SC70(L/F; Category: XDP; Change to: 73.01G66.DHH; DESCRIPTIO: IC CMOS NC7SZ66P5X_NL SC70(L/F; GREENDFACTOR: R2_SA;; Note: (1) The same as L82TT1 (2) Alternate also the same as L82TT1.; Package Type: DISCRET-G; Part Number: 73.7SZ66.AAH; Part Type: DISCRET-G; SPEC: http://wpqssvr.wistron.com.tw:7001/wpqs/servlet/COM.qpart.Attachment?PartNumber=73.7SZ66.AAH; VENDORPARTNUMBER: NC7SZ66P5X_NL
U146 = GTL2034PW-GP: IC XLATOR GTL2034PW TSSOP 14P; GREENDFACTOR: R_C;; Package Type: TTL-G3; Part Number: 71.02034.00W; SPEC: http://wpqssvr.wistron.com.tw:7001/wpqs/servlet/COM.qpart.Attachment?PartNumber=71.02034.00W
D15 = BAT54-7-F-GP: DIODE S.B BAT54-7-F SOT23 3P; GREENDFACTOR: R2_SA;HF_SA;; POP?: NOPOP; Part Number: 83.00054.Z81; Part Type: DISCRET-G; SPEC: http://wpqssvr.wistron.com.tw:7001/wpqs/servlet/COM.qpart.Attachment?PartNumber=83.00054.Z81
D16-D19 D33-D35 = BAT54-7-F-GP: DIODE S.B BAT54-7-F SOT23 3P; GREENDFACTOR: R2_SA;HF_SA;; Part Number: 83.00054.Z81; Part Type: DISCRET-G; SPEC: http://wpqssvr.wistron.com.tw:7001/wpqs/servlet/COM.qpart.Attachment?PartNumber=83.00054.Z81
CLIP1 CLIP2 = AMP-CON2-13-GP: ANCHOR 2P G800U305032D1EU; GREENDFACTOR: R2_SA;; Package Type: CONN-G5; Part Number: 25.60037.081; SPEC: http://wpqssvr.wistron.com.tw:7001/wpqs/servlet/COM.qpart.Attachment?PartNumber=25.60037.081
H1-H7 = GEN276X162R197X296-6-F-A-GP: SCREW HOLE TYPE A; GREENDFACTOR: R2_C;; Package Type: DISCRET-G8; Part Number: ZZ.SCREW.511; SPEC: http://wpqssvr.wistron.com.tw:7001/wpqs/servlet/COM.qpart.Attachment?PartNumber=ZZ.SCREW.511
H8 = STFT363B238R224H453-GP: THUMB SCREW SMT M3X0.5 L4.6; GREENDFACTOR: R2_C;; Part Number: 086.2AT24.04R6; Part Type: DISCRET-GC1; SPEC: http://wpqssvr.wistron.com.tw:7001/wpqs/servlet/COM.qpart.Attachment?PartNumber=086.2AT24.04R6
H10 = HOLE: FOR SCREW HOLE PTH; GREENDFACTOR: Regular;; Part Number: ZZ.0HOLE.XXX; Part Type: DISCRETE; SPEC: http://wpqssvr.wistron.com.tw:7001/wpqs/servlet/COM.qpart.Attachment?PartNumber=ZZ.0HOLE.XXX

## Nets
GND: C714.2 C715.2 C716.2 C717.2 C722.2 C727.2 C909.2 CLIP1.1 CLIP1.2 CLIP2.1 CLIP2.2 H1.1 H1.2 H1.3 H1.4 H1.5 H1.6 H2.1 H2.2 H2.3 H2.4 H2.5 H2.6 H3.1 H3.2 H3.3 H3.4 H3.5 H3.6 H4.1 H4.2 H4.3 H4.4 H4.5 H4.6 H5.1 H5.2 H5.3 H5.4 H5.5 H5.6 H6.1 H6.2 H6.3 H6.4 H6.5 H6.6 H7.1 H7.2 H7.3 H7.4 H7.5 H7.6 H8.1 H10.1 PC1087.2 PC1088.2 PC1089.2 PC1090.2 PC1094.1 PC1096.2 PC1097.2 PC1222.1 PC1227.1 PC1228.1 PC1229.2 PC1280.2 PC1281.1 PC1282.1 PC1283.1 PC1362.2 PC1363.2 PC1364.2 PC1369.2 PC1370.2 PC1371.2 PC1372.2 PC1373.1 PC1374.1 PC1375.1 PC1394.2 PC1395.2 PC1396.2 PC1403.2 PC1404.2 PC1405.2 PC1428.2 PC1429.2 PC1430.1 PC1435.2 PC1492.1 PCN1.3 PQ5.B PQ5.C PR24.2 PR25.2 PR26.2 PR1922.2 PR1923.2 PR1924.2 PR1926.1 PU1.1(GND) PU1.20(ISEN6N) PU1.38(GND) PU1.39(GND) PU1.41(GND) PU1.42(GND) PU1.44(GND) PU1.49(GND) PU178.4(AGND) PU178.12(PGND) PU178.13(PGND) PU178.14(PGND) PU178.15(PGND) PU178.28(PGND) PU178.32(PGND) PU178.34(PGND) PU179.4(AGND) PU179.12(PGND) PU179.13(PGND) PU179.14(PGND) PU179.15(PGND) PU179.28(PGND) PU179.32(PGND) PU179.34(PGND) PU180.4(AGND) PU180.12(PGND) PU180.13(PGND) PU180.14(PGND) PU180.15(PGND) PU180.28(PGND) PU180.32(PGND) PU180.34(PGND) R470.2 R612.2 R626.2 R1213.2 R1214.2 U69.2(GND) U70.2(GND) U71.3(GND) U72.3(GND) U146.7(GND) U146.8(GND) U146.11(GND) ; also on sheet 1 2 3 4 5 6 7 8 9 10 11 12 13 14 15 16 17 18 19 20 21 22 23 24 25 26 27 28 29 30 31 32 33 34 35 36 37 47 49 50 51 52 53 54 55 56 57 58 59 60 61 62 63 64 65 66 69 70 71 73 74 75 76 78 79 80 81 82 83 84 86 87 88 89 90 91 92 93 94 95 96 97 98 99 100 101 102 103 104 105 106 107 108 109 110 111 112 113 114 115 116 117 118 119 128 129 138 139 159 160 161 166 168 169 170 171 172 173 174 175 176 177 180 181 182 183 184
P1V5_PCH: D16.1 ; also on sheet 8 87 91 166 173
P1V05_PCH: D15.1 ; also on sheet 10 87 173 175
P1V05_STBY_PCH: D35.1 ; also on sheet 9 76 87
P3V3: C714.1 C715.1 C716.1 C717.1 C722.1 C727.1 C909.1 D15.2 D16.2 D17.1 R1006.1 R1007.1 U69.5(VCC) U70.5(VCC) U71.5(VCC) U72.5(VCC) U146.14(VCC) ; also on sheet 1 3 8 48 49 52 54 58 65 74 76 78 83 84 87 90 91 94 95 96 100 101 102 161 166 168 173 174 177 180 181 182 183
P3V3_STBY: D18.2 D19.2 D33.2 D34.2 D35.2 PR42.2 PR43.2 PR44.2 PR1911.1 PR1914.2 PR1915.2 ; also on sheet 2 3 5 6 8 9 10 11 12 15 16 17 20 21 22 25 26 27 30 31 33 34 35 37 47 49 50 51 52 54 55 59 60 61 62 63 64 65 66 69 70 71 72 73 74 76 79 83 84 87 88 89 90 91 92 93 94 95 96 97 98 99 159 161 166 168 173 174 176 177 179 180 182 183 184
P5V: D17.2 ; also on sheet 59 66 69 76 80 82 176
P5V_STBY: PC1222.2 PC1228.2 PC1281.2 PC1283.2 PC1373.2 PC1375.2 PR2174.1 PR2178.1 PR2181.1 PU178.29(PVCC) PU179.29(PVCC) PU180.29(PVCC) ; also on sheet 4 5 6 8 14 15 19 20 24 25 29 30 33 34 37 59 61 65 69 76 95
PVCCIN_CPU0: PG28.2 PG30.2 PG34.2 PL75.2(F) PL76.2(F) PL77.2(F) ; also on sheet 36 37 130
PVCCIN_CPU0_ALERT: PR1934.1 PU1.15(ALERT#)
PVCCIN_CPU0_BOOT1: PR2205.1 PU178.5(BOOT)
PVCCIN_CPU0_BOOT2: PR2209.1 PU179.5(BOOT)
PVCCIN_CPU0_BOOT3: PR2215.1 PU180.5(BOOT)
PVCCIN_CPU0_EN: PR1917.2 ; also on sheet 51
PVCCIN_CPU0_EN1: PR42.1 PU178.31(EN)
PVCCIN_CPU0_EN2: PR43.1 PU179.31(EN)
PVCCIN_CPU0_EN3: PR44.1 PU180.31(EN)
PVCCIN_CPU0_FAULT: PR1916.1 PU1.46(FAULT1)
PVCCIN_CPU0_GH1: PTP8.1 PU178.6(GH)
PVCCIN_CPU0_GH2: PTP10.1 PU179.6(GH)
PVCCIN_CPU0_GH3: PTP12.1 PU180.6(GH)
PVCCIN_CPU0_GL1: PTP7.1 PU178.27(GL#27)
PVCCIN_CPU0_GL2: PTP9.1 PU179.27(GL#27)
PVCCIN_CPU0_GL3: PTP11.1 PU180.27(GL#27)
PVCCIN_CPU0_IMON: PTP1.1 PU1.22(IMON/FAULT2)
PVCCIN_CPU0_ISEN1N: PC7321.2 PR6627.2 PU1.34(ISEN1N)
PVCCIN_CPU0_ISEN1P: PC7321.1 PG28.1 PU1.35(ISEN1P)
PVCCIN_CPU0_ISEN2N: PC7322.2 PR6630.2 PU1.31(ISEN2N)
PVCCIN_CPU0_ISEN2P: PC7322.1 PG30.1 PU1.32(ISEN2P)
PVCCIN_CPU0_ISEN3N: PC7323.2 PR6632.2 PU1.28(ISEN3N)
PVCCIN_CPU0_ISEN3P: PC7323.1 PG34.1 PU1.29(ISEN3P)
PVCCIN_CPU0_ISEN4N: PC7324.2 PU1.25(ISEN4N) ; also on sheet 37
PVCCIN_CPU0_ISEN4P: PC7324.1 PU1.26(ISEN4P) ; also on sheet 37
PVCCIN_CPU0_ISEN5N: PC7325.2 PU1.23(ISEN5N) ; also on sheet 37
PVCCIN_CPU0_ISEN5P: PC7325.1 PU1.24(ISEN5P) ; also on sheet 37
PVCCIN_CPU0_PG: PR1914.1 PR1918.1 PU1.9(VR_READY)
PVCCIN_CPU0_PHASE1: PC1221.2 PU178.7(PHASE)
PVCCIN_CPU0_PHASE1_R: PC1221.1 PR2205.2
PVCCIN_CPU0_PHASE2: PC1234.2 PU179.7(PHASE)
PVCCIN_CPU0_PHASE2_R: PC1234.1 PR2209.2
PVCCIN_CPU0_PHASE3: PC1284.2 PU180.7(PHASE)
PVCCIN_CPU0_PHASE3_R: PC1284.1 PR2215.2
PVCCIN_CPU0_PWM1: PU1.3(PWM1) PU178.1(PWM)
PVCCIN_CPU0_PWM2: PU1.4(PWM2) PU179.1(PWM)
PVCCIN_CPU0_PWM3: PU1.5(PWM3) PU180.1(PWM)
PVCCIN_CPU0_PWM4: PU1.6(PWM4) ; also on sheet 37
PVCCIN_CPU0_PWM5: PU1.7(PWM5) ; also on sheet 37
PVCCIN_CPU0_SADDRL: PR1924.1 PU1.30(SADDR_L)
PVCCIN_CPU0_SADDRM: PR1923.1 PU1.27(SADDR_M)
PVCCIN_CPU0_SW#1: PG27.2 PL75.1(S) PU178.16(SW#16) PU178.17(SW#17) PU178.18(SW#18) PU178.19(SW#19) PU178.20(SW#20) PU178.21(SW#21) PU178.22(SW#22) PU178.23(SW#23) PU178.24(NC#24) PU178.25(NC#25) PU178.26(NC#26)
PVCCIN_CPU0_SW#1_N: PG27.1 PR6626.2
PVCCIN_CPU0_SW#1_R: PR6626.1 PR6627.1
PVCCIN_CPU0_SW#2: PG29.2 PL76.1(S) PU179.16(SW#16) PU179.17(SW#17) PU179.18(SW#18) PU179.19(SW#19) PU179.20(SW#20) PU179.21(SW#21) PU179.22(SW#22) PU179.23(SW#23) PU179.24(NC#24) PU179.25(NC#25) PU179.26(NC#26)
PVCCIN_CPU0_SW#2_N: PG29.1 PR6629.2
PVCCIN_CPU0_SW#2_R: PR6629.1 PR6630.1
PVCCIN_CPU0_SW#3: PG33.2 PL77.1(S) PU180.16(SW#16) PU180.17(SW#17) PU180.18(SW#18) PU180.19(SW#19) PU180.20(SW#20) PU180.21(SW#21) PU180.22(SW#22) PU180.23(SW#23) PU180.24(NC#24) PU180.25(NC#25) PU180.26(NC#26)
PVCCIN_CPU0_SW#3_N: PG33.1 PR6631.2
PVCCIN_CPU0_SW#3_R: PR6631.1 PR6632.1
PVCCIN_CPU0_TMON1: PR24.1 PU178.30(PHFLT#)
PVCCIN_CPU0_TMON2: PR25.1 PU179.30(PHFLT#)
PVCCIN_CPU0_TMON3: PR26.1 PU180.30(PHFLT#)
PVCCIN_CPU0_TSEN: PC1492.2 PR1928.1 PU1.33(TSEN)
PVCCIN_CPU0_TSEN_R: PC1430.2 PQ5.E PR1928.2
PVCCIN_CPU0_VADDR: PR1922.1 PU1.17(VADDR)
PVCCIN_CPU0_VCC1: PC1227.2 PR2174.2 PR2227.2 PU178.3(VCC)
PVCCIN_CPU0_VCC2: PC1282.2 PR2178.2 PR2228.2 PU179.3(VCC)
PVCCIN_CPU0_VCC3: PC1374.2 PR2181.2 PR2229.2 PU180.3(VCC)
PVCCIN_CPU0_VCLK: PR1936.1 PU1.13(VCLK)
PVCCIN_CPU0_VD15: PC1089.1 PC1090.1 PU1.48(VD15)
PVCCIN_CPU0_VDD: PC1087.1 PC1088.1 PR1911.2 PU1.37(VDD)
PVCCIN_CPU0_VDIO: PR1935.1 PU1.14(VDIO)
PVCCIN_CPU0_VIN: PC1229.1 PC1280.1 PC1362.1 PC1363.1 PC1364.1 PC1369.1 PC1370.1 PC1371.1 PC1372.1 PC1394.1 PC1395.1 PC1396.1 PC1403.1 PC1404.1 PC1405.1 PC1428.1 PC1429.1 PC1435.1 PR1925.1 PU178.8(VIN) PU178.9(VIN) PU178.10(VIN) PU178.11(VIN) PU178.33(VIN) PU179.8(VIN) PU179.9(VIN) PU179.10(VIN) PU179.11(VIN) PU179.33(VIN) PU180.8(VIN) PU180.9(VIN) PU180.10(VIN) PU180.11(VIN) PU180.33(VIN) ; also on sheet 36 37
PVCCIN_CPU0_VINSEN: PC1094.2 PR1925.2 PR1926.2 PU1.36(VINSEN)
PVCCIN_CPU0_VR_EN: PR1917.1 PU1.10(VR_EN)
PVCCIN_CPU0_VSENN: PC1095.2 PR1929.2 PU1.19(VSENN)
PVCCIN_CPU0_VSENP: PC1095.1 PR1927.2 PU1.18(VSENP)
PVCCIN_CPU0_ZCD#1: PR2227.1 PU178.2(NC#2)
PVCCIN_CPU0_ZCD#2: PR2228.1 PU179.2(NC#2)
PVCCIN_CPU0_ZCD#3: PR2229.1 PU180.2(NC#2)
PVCCIO: PC1096.1 PC1097.1 PR1931.1 PR1932.1 PR1933.1 R615.2 R702.1 R1000.1 R1001.1 R1003.1 R1237.1 R1245.1 R1246.1 R1247.1 ; also on sheet 11 16 26 35 47 68 87 97 100 101 102 103 120 129 130 139 160 173 177 179 182
PVDDQ_AB: D34.1 ; also on sheet 28 30 52 97 116 117 118 119 130 139
PVDDQ_CD: D33.1 ; also on sheet 23 25 97 112 113 114 115 130 139
PVDDQ_EF: D19.1 ; also on sheet 18 20 97 108 109 110 111 120 129
PVDDQ_GH: D18.1 ; also on sheet 13 15 97 104 105 106 107 120 129
FM_CPU0_SKTOCC_LVT3_N: R300.1 ; also on sheet 51 139 179
FM_CPU1_SKTOCC_LVT3_N: R328.1 ; also on sheet 51 129 179
GTL2034_VREF: R470.1 R1247.2 U146.4(VREF)
IRQ_PVCCIN_CPU0_VRHOT_LVT3_N: PR1915.1 PU1.47(VR_HOT#) ; also on sheet 177 181
PD_XDP_BUF_BI0: R1214.1 U146.13(BI0)
PD_XDP_BUF_BI2: R1213.1 U146.10(BI2)
PU_CPU0_SKTOCC_FRBY: R303.2 R1006.2
PU_CPU1_SKTOCC_FRBY: R329.2 R1007.2
PWRGD_PVCCIN_CPU0: PR1918.2 ; also on sheet 51 58
SMB_VR_STBY_LVC3_CLK: PCN1.1 PU1.12(SCL) ; also on sheet 16 21 26 31 35 74 161
SMB_VR_STBY_LVC3_DATA: PCN1.2 PU1.11(SDA) ; also on sheet 16 21 26 31 35 74 161
SVID_ALERT_CPU0_N: PR1931.2 PR1934.2 ; also on sheet 26 31 139
SVID_CLK_CPU0: PR1933.2 PR1936.2 ; also on sheet 26 31 139
SVID_DIO_CPU0: PR1932.2 PR1935.2 ; also on sheet 26 31 139
TP_XDP_BUF_BO0: TP313.1 U146.2(BO0)
TP_XDP_BUF_BO2: TP314.1 U146.5(BO2)
VR_FAIL_PVCC_CPU_N: PR1916.2 ; also on sheet 16 21 26 31 35 74
VSENSE_PVCCIN_CPU0_N: PR1929.1 ; also on sheet 36 130
VSENSE_PVCCIN_CPU0_P: PR1927.1 ; also on sheet 36 130
XDP_CPU0_PRDY_G_N: R431.1 R1245.2 U146.3(BO1) ; also on sheet 47 139
XDP_CPU0_PREQ_G_N: R426.2 R702.2 U146.9(BI3) ; also on sheet 47 139
XDP_CPU0_SKTOCC_N: R300.2 R303.1 U69.6(S) U71.2(A)
XDP_CPU0_TDI_G: R1001.2 U69.3(B0) ; also on sheet 139
XDP_CPU0_TDO_G: U70.1(B1) U72.1(A) ; also on sheet 139
XDP_CPU1_PRDY_G_N: R431.2 R1237.2 U146.12(BI1) ; also on sheet 129
XDP_CPU1_PREQ_G_N: R426.1 R1246.2 U146.6(BO3) ; also on sheet 129
XDP_CPU1_SKTOCC_N: R328.2 R329.1 U70.6(S) U71.1(B)
XDP_CPU1_TDI_G: R1000.2 U69.1(B1) U72.2(B) ; also on sheet 129
XDP_CPU1_TDO_G: U70.3(B0) ; also on sheet 129
XDP_CPU_EN: U71.4(Y) U72.4(OE)
XDP_CPU_TCK_G: R612.1 ; also on sheet 47 129 139
XDP_CPU_TDI: U69.4(A) ; also on sheet 47
XDP_CPU_TDO: R1003.2 U70.4(A) ; also on sheet 47
XDP_CPU_TMS_G: R615.1 ; also on sheet 47 129 139
XDP_CPU_TRST_G_N: R626.1 ; also on sheet 47 129 139

Not connected (* = marked no-connect by the designer): D15 3*; D16 3*; D17 3*; D18 3*; D19 3*; D33 3*; D34 3*; D35 3*; PU1 2(DNC#2)* 8(PWM6)* 16(RESET#)* 21(ISEN6P)* 40(DNC#40)* 43(DNC#43)* 45(DR_EN)*; PU178 35(GL#35)*; PU179 35(GL#35)*; PU180 35(GL#35)*; U146 1(NC#1)*

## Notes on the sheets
sheet 38
- PVCCIN_CPU0_MOSFET_1
- FP1007R3-R15-R
  150nH/0.29mohm/61A
  7.8*10.2*7.3 mm
- FP1007R3-R15-R
  150nH/0.29mohm/61A
  7.8*10.2*7.3 mm
- FP1007R3-R15-R
  150nH/0.29mohm/61A
  7.8*10.2*7.3 mm
sheet 39
- Power rail : PVCCIN_CPU0
  VID : 1.85 V / 1.7VbootSVID
  Controller : PX3746H
  TDC : 88 A
  Max : 190 A
  OCP : 210 A
  I2C address :  04
  SVID address : 00
  Platform : Grantley-EP 2S/4S skt R3
  CPU : HSX/BDX-EP 2S 145W
- Come from INFINEON  PX3746 datasheet
- change to 21.63204.105
- Vendor PMBus Debug port
- Routed As Differential Pair
- Routed As Differential Pair
- Routed As Differential Pair
- Routed As Differential Pair
- Routed As Differential Pair
- Measurement point for Bode
- CPU0 I2C address:04
- Routed As Differential Pair
- close Phase 1 between phase 2
- Use Daisy Chain
- PDG P.252
sheet 40
- CLOCK BLOCK DIAGRAM
- DB1900Z
- M_A_CLK_DP/N_[0]
- DIMM A0-A1
- DIF_IN
  DIF_IN_N
- DIF_5
  DIF_5_N
- Differential
- CLK_100M_CPU0_BCLK0_DP/N
- M_B_CLK_DP/N_[0]
- DIMM B0-B1
- DIF_6
  DIF_6_N
- Differential
- CLK_100M_CPU0_BCLK1_DP/N
- M_C_CLK_DP/N_[0]
- DIMM C0-C1
- SMC-CONN60A-GP
- M_D_CLK_DP/N_[0]
- P.180
- DIMM D0-D1
- P.25- 37
- M_E_CLK_DP/N_[0]
- DIMM E0-E1
- DIF_7
  DIF_7_N
- CLK_100M_CPU1_BCLK0_DP/N
- Differential
- M_F_CLK_DP/N_[0]
- DIMM F0-F1
- DIF_8
  DIF_8_N
- Differential
- CLK_100M_CPU1_BCLK1_DP/N
- M_G_CLK_DP/N_[0]
- DIMM G0-G1
- DIF_0
  DIF_0_N
- M_H_CLK_DP/N_[0]
- Differential
- NC
- DIMM H0-H1
- P.38 - 61
- WELLSBURG
- P.82 - 93
- R274/R275 0R
- DIF_1    DIF_1_N
  DIF_2    DIF_2_N
- Differential
- CLK_100M_RISER1_PE1_DP/N
- CLK_100M_PCH_DB1900_R_DP/N
- CLKOUT_DMI_P1/N1
- Differential
- CLK_100M_RISER1_PE2_DP/N
- R277/278 0R
- P.80
- PCIE RISER
- CLK_100M_PCH_XDP_DP/N
- Differential
- CLK_100M_MEZZ1_DP/N
- CLKOUT_ITPXDP_P/N
- DIF_3    DIF_3_N
  DIF_4    DIF_4_N
- P.138
- Differential
- CLK_100M_MEZZ2_DP/N
- CLK_33K_SUSCLK_PLD
- MEZZ CONNECTOR
- 10K
- SUSCLK/GPIO62
- CPLD1
- CLK_96M_PCH_DP/N
- DIF_9
  DIF_9_N
- Differential
- P.79
- CLKIN_DOT96_P/N
- CLKIN_CPY_P/N
- CLK_100M_PCH_CPY_DP/N
- NC
- DIF_10
  DIF_10_N
- CLKOUT_PCI4
- CLK_33M_PCH_CPLD_R
- CPLD2
- Differential
- NC
- R440 22.1R
- DIF_11
  DIF_11_N
- CLKOUT_PCI3
- CLK_33M_PCH_TPM_CONN_R
- Differential
- CLK_100M_RISER1_PE3_DP/N
- R959 22.1R
- CLKOUT_PCI2
- CLK_33M_PCH_BMC_LPC_R
- 10K
- DIF_12
  DIF_12_N
- Differential
- CLK_100M_RISER2_PE1_DP/N
- CLK_100M_PCH_SATAX_DP/N
- CLKIN_SSATA_P/N
- TP_CLKOUT_PCI_1
- MID-PLANE CONNECTOR
- CLKOUT_PCI1
- TP327
- DIF_13
  DIF_13_N
- P.81
- 10K
- CLK_100M_PCH_SATA_DP/N
- Differential
- NC
- CLKIN_SATA_P/N
- CLKOUT_PCI0
- CLK_33M_PCH_TPM_R
- P.96
- DIF_14
  DIF_14_N
- Differential
- CLK_100M_PE_D_DP/N
- NGFF
- 10K
- CLKIN_PCILOOPBACK
- CLK_14M_PCH
- DIF_15
  DIF_15_N
- Differential
- CLK_100M_NIC_PE_DP/N
- Springville
  (INTEL I210)
- REFCLK14IN
- R379
- DIF_16
  DIF_16_N
- P.125- 127
- Differential
- NC
- BMC
- P.108 - 110
- DIF_17
  DIF_17_N
- Differential
- NC
- LCLK
- DIF_18
  DIF_18_N
- Differential
- CLK_100M_PCH_CPY_DP/N
- AST1250
- TPM
  Conn
- 9ZX21901BKLFT-1-GP
- P.131
- P.103
- CLK_32K_SUSCLK_NGFF
- P.96
- 32_768KHZ
- NGFF
- CKMNG
- 25MHZ_1
- P.137
- CLK_25M_CPLD
- CPLD
- 25MHZ_0
- NOPOP
- TP_CLK7_50M_CKMNG
- RMII7
- TP299
- TP_CLK6_50M_CKMNG
- RMII6
- TP300
- RMII5
- RMII4
- RMII3
- CLK_50M_NIC
- CLK_50M_BMC_MAC1
- RMII2
- BMC
  AST1250
- CLK_50M_BMC_MAC2
- RMII1
- RMII0
- CLK_50M_BMC_NCSI
- MEZZ CONNECTOR
- P.108 - 110
- DOT96SST
- P.79
- DOT96SSC
- CPUCLKT0
- CPUCLKC0
- ICS9FGP202YKLF-GP
- P.134
- XTAL-25MHZ
sheet 41
- SMBUS BLOCK DIAGRAM - CPU & PCH
- P.123
- P.134
- P.131
- P.82 - 93
- P.108 - 110
- SMB ADDRESS: 0XAC
- I2C Add = D0 (h)
- P.180
- SMBUS ADDRESS= 0xD8 - 0xD9
- P3V3_STBY
- BMC1A
- U45
- U35
- XDPCN1
- P3V3
- DB1
- PCH
- BMC
  SMBus5
- FRU
  MEMORY
- DB1900Z -
  CLOCK BUFFER
- CKMNG
- CPU - XDP
- R1585/R1595
- R543/R544
  4k7£[
- U41
- R619/R618
  4k7£[
- SMB_CLK/DATA
- SMB_CLK/DATA
- 0£[
- SMB_HOST_STBY_LVC3_CLK/DATA
- BSS138DW
- SMB_HOST_3V3_CLK/DATA
- P.108 - 110
- P.140
- P.144
- P.148
- P.153
- P.158
- P.163
- P3V3
- P3V3_STBY
- BMC1A
- CPU0 I2C
  address:04
- CPU1 I2C
  address:24
- PVDDQ_AB I2C
  address:08
- PVDDQ_CD I2C
  address:0C
- PVDDQ_EF I2C
  address:10
- PVDDQ_GH I2C
  address:14
- BMC
  SMBus4
- PU1
- PU7
- PU13
- PU19
- PU25
- PU31
- PX3746HDN
- PX3746HDN
- PX3244HDM
- PX3244HDM
- PX3244HDM
- PX3244HDM
- R623/R622
  4k7£[
- R875/R874
  4k7£[
- SMB_0_ME_PCH_SCL/SDA
- SMB_VR_STBY_LVC3_CLK/DATA
- MEXP_SMBCLK0/DATA0
- P3V3
- R879/R878
  4k7£[
- R284/R263
- MEXP_SMBCLK1/DATA1
- SMB_1_ME_PCH_SCL/SDA
- 0£[
- NOPOP
- P3V3
- R877/R876
  4k7£[
- R262/R261
- MEXP_SMBCLK2/DATA2
- SMB_2_ME_PCH_SCL/SDA
- 0£[
- NOPOP
- DMI
- P.52
- P.53
- P.54
- P.55
- P.25- 37
- I2C Address = A0
- I2C Address = A2
- I2C Address = A8
- I2C Address = AA
- PVCCIO
- PVPP_AB
- DIMMA1
- DIMMA2
- DIMMB1
- DIMMB2
- CPU0
- CPU0
  CHA-1
- CPU0
  CHA-2
- CPU0
  CHB-1
- CPU0
  CHB-2
- R567/R568
  240£[
- R569/R570
  1k£[
- R572/R573
- U36
- DDR_SCL/SDA_C1
- SMB_DDR_AB_SCL/SDA_G
- 10£[
- PCA9617ADP
- SMB_DDR_AB_SCL/SDA_LVC2V5
- P.56
- P.57
- P.58
- P.59
- I2C Address = A0
- I2C Address = A2
- I2C Address = A8
- I2C Address = AA
- PVCCIO
- PVPP_CD
- DIMMC1
- DIMMC2
- DIMMD1
- DIMMD2
- CPU0
  CHC-1
- CPU0
  CHC-2
- CPU0
  CHD-1
- CPU0
  CHD-2
- R579/R580
  240£[
- R574/R581
  1k£[
- R585/R588
- U37
- DDR_SCL/SDA_C23
- SMB_DDR_CD_SCL/SDA_G
- 10£[
- PCA9617ADP
- SMB_DDR_CD_SCL/SDA_LVC2V5
- QPI
- P.60
- P.61
- P.62
- P.63
- P.38 - 61
- I2C Address = A0
- I2C Address = A2
- I2C Address = A8
- I2C Address = AA
- PVCCIO
- PVPP_EF
- DIMME1
- DIMME2
- DIMMF1
- DIMMF2
- CPU1
- CPU1
  CHE-1
- CPU1
  CHE-2
- CPU1
  CHF-1
- CPU1
  CHF-2
- R596/R597
  240£[
- R582/R584
  1k£[
- R602/R603
- U38
- DDR_SCL/SDA_C1
- SMB_DDR_EF_SCL/SDA_G
- 10£[
- PCA9617ADP
- SMB_DDR_EF_SCL/SDA_LVC2V5
- I2C Address = A0
- P.64
- I2C Address = A2
- P.65
- I2C Address = A8
- P.66
- I2C Address = AA
- P.67
- PVCCIO
- PVPP_GH
- DIMMG1
- DIMMG2
- DIMMH1
- DIMMH2
- CPU1
  CHG-1
- CPU1
  CHG-2
- CPU1
  CHH-1
- CPU1
  CHH-2
- R609/R610
- R604/R605
  240£[
- U39
- R586/R587
  1k£[
- DDR_SCL/SDA_C23
- SMB_DDR_GH_SCL/SDA_G
- 10£[
- PCA9617ADP
- SMB_DDR_GH_SCL/SDA_LVC2V5
sheet 42
- SMBUS BLOCK DIAGRAM - BMC
- R1416/R1417
- LAN_SMB_CLK_MEZZ/
  LAN_SMB_DAT_MEZZ
- R699/R700
- LAN_SMB_CLK_PCIE/
  LAN_SMB_DAT_PCIE
- R1013/R1014
- LAN_SMB_CLK_I210/
  LAN_SMB_DAT_I210
- P.108 - 110
- P3V3_STBY
- 0£[
- 0£[
- 33£[
- P3V3_STBY
- P.82 - 93
- BMC
- JP8
- MEZCN1
- PCIE1
- LAN1
- PCH
- P.79
- MEZZ
  CONNECTOR
- P.80
- PCIE
  RISER
- P.125- 127
- INTEL
  I210
- I2C/SMBus
- R2038/R2039
  1k£[
- R2035/R2034
  1k£[
- 400kHz
- LAN_SMB_CLK/DAT
- SMB_SMLINK0_STBY_LVC3_CLK/DATA
- SCL1/SDA1
- SML0CLK/DATA
- R2100/R2101
- MB0_PMBUS_PCH_SML1CLK_R/
  MB0_PMBUS_PCH_SML1DATA_R
- R717/R721
- PMBUS_CLK/
  PMBUS_DATA
- P3V3_STBY
- 0£[
- 0£[
- P3V3_STBY
- JP9
- P.129
- U2
- P.81
- MIDCN2
- HSC
  ADM1278
- MID-PLANE
  CONNECTOR
- R2037/R2036
  1k£[
- R172/R173
  4k7£[
- 400kHz
- R1597/R1598
- SCL2/SDA2
- SMB_PMBUS_BMC_STBY_LVC3_CLK/DATA
- ADDRESS : 0X22
- 0£[
- SML1_CLK/DATA
- SML1CLK/DATA
- NOPOP
- JP10
- 1MHz
- SCL3/SDA3
- SMB_SMLINK0_STBY_LVC3_CLK/DATA
- R1921/R1920
- PVCCIN_CPU0_SCL/
  PVCCIN_CPU0_SDA
- R1961/R1960
- PVCCIN_CPU1_SCL/
  PVCCIN_CPU1_SDA
- R2007/R2006
- PVDDQ_AB_SCL/
  PVDDQ_AB_SDA
- R2039/R2038
- PVDDQ_CD_SCL/
  PVDDQ_CD_SDA
- R2074/R2073
- PVDDQ_EF_SCL/
  PVDDQ_EF_SDA
- R2138/R2137
- PVDDQ_GH_SCL/
  PVDDQ_GH_SDA
- P3V3_STBY
- 0£[
- 0£[
- 0£[
- 0£[
- 0£[
- 0£[
- JP11
- PU1
- PU7
- PU13
- PU19
- PU25
- PU31
- P.140
- PX3746HDN
- P.144
- PX3746HDN
- P.148
- PX3244HDM
- P.153
- PX3244HDM
- P.158
- PX3244HDM
- P.163
- PX3244HDM
- R874/R875
  1k£[
- SCL4/SDA4
- 400kHz
- SMB_VR_STBY_LVC3_CLK/DATA
- CPU0 I2C address:04
- CPU1 I2C address:24
- PVDDQ_AB I2C address:08
- PVDDQ_CD I2C address:0C
- PVDDQ_EF I2C address:10
- PVDDQ_GH I2C address:14
- P3V3
- P3V3_STBY
- U35
- XDPCN1
- JP12
- P.134
- P.180
- R623/R622
  4k7£[
- CKMNG
- CPU - XDP
- SMB_0_ME_PCH_SCL/SDA
- MEXP_SMBCLK0/DATA0
- R543/R544
  4k7£[
- 100kHz
- R1585/R1595
- SCL5/SDA5
- SMB_HOST_STBY_LVC3_CLK/DATA
- I2C Add = D0 (h)
- P3V3
- 0£[
- SMB_CLK/DATA
- SMBCLK/DATA
- U41
- R619/R618
  4k7£[
- DB1
- BSS138DW
- SMB_HOST_3V3_CLK/DATA
- P.131
- DB1900Z -
  CLOCK BUFFER
- SMBUS ADDRESS= 0xD8 - 0xD9
- SMB_TEMP_FRONT_SCL_R/
  SMB_TEMP_FRONT_SDA_R
- SMB_TEMP_BACK_SCL_R/
  SMB_TEMP_BACK_SDA_R
- R711/R724
- 0£[
- R896/R899
- 0£[
- CPLD2
- U45
- P3V3_STBY
- P.137
- P.123
- TEMP2
- TEMP1
- CPLD
- FRU
  MEMORY
- P.117
- THERMAL
  SENSOR
- P.117
- THERMAL
  SENSOR
- 400kHz
- R2046/R2040
  1k£[
- SCL6/SDA6
- SMB_SENSOR_CLK/DAT
- I2C Address: 0X9C  110
- I2C Address: 0X9E  111
- SMB ADDRESS: 0XA6
- TEMP2 Place on Front side
- TEMP1 Place on Rear side
- HOST_SLOT1_SCL/
  HOST_SLOT1_SDA
- R480/R482
- 0£[
- P3V3_STBY
- PCIE1
- P.80
- PCIE
  RISER
- R2055/R2095
  2k2£[
- SCL7/SDA7
- 100kHz
- SMB_MAIN_CLK/DATA
- R1522/R1523
- SMB6_RISER2_CLK_R/
  SMB6_RISER2_DAT_R
- P3V3_STBY
- 0£[
- MEZCN1
- R2042/R2049
  2k2£[
- P.79
- MEZZ
  CONNECTOR
- 400kHz
- SCL8/SDA8
- SMB_BMC_MEZZ_SCL/SDA
- P3V3_STBY
- R2041/R2048
  2k2£[
- SMB_BMC_RSVD_SCL/SDA
- SCL9/SDA9
- SCL7/SDA7
sheet 43
- 12/30
  1. Change P12V to P12V_STBY
  2. Add ESD solution
sheet 44
- SCREW HOLE
- WELLSBURG HEATSINK CLIP
- SCREW HOLE
- FAB1 20150309
- FAB1 REV024 20150429
- SCREW HOLE
sheet 45
- POWER SEQUENCE CONTROL
sheet 46
- Pull up should be placed near the last processor on the trace
  If TMS is forking to 2 traces, each traces should be terminated with a pull up
- CPU - JTAG
- placed termination to within 200ps (roughly 1100 mil) of last processor
  on the trace.
- 2-Sockets system:
   ¡X 	Connect to MUX/FET Switch and then to
  processor(0)TDI, and each processor TDI pin in
  the chain need to be pulled up to VCCIO via 75ohm
  ¡Ó5% resistor
- PDG P.609
- Pull down should be placed near the last processor on the trace
  CAD NOTE: Placed termination to within 200ps (roughtly 1100 mils)
            of last processor on the trace.
- 2-sockets system
  Connect to MUX and then to processor(1) and
  pull up to VCCIO via a 75 ohm ∮5% resistor
  near XDP pin
- Connect to processor(s) and then pull
  down to ground via a 51 ohm ∮5% resistor.
- BYPASS CHAIN CONTROL
- POP
- OPERATIONAL STATE
- POP
- OPERATIONAL STATE
- FORCES BYPASS OF CPU0
  (JTAG)
- FORCES BYPASS OF CPU1
  (JTAG)
- R303
- R329
- R300
- NORMAL OPERATION
- R328
- NORMAL OPERATION
- 100 ohm - Trace length less than 4.3ns (24000mils)
- 200 ohm - 48000mils > Trace length > 24000mils
- PDG P.627
- Placed termination to within 200ps
  (roughly 1100 mil) of last processor
  on the trace.
